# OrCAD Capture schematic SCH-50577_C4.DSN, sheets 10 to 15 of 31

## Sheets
10 08 SD Card: size C
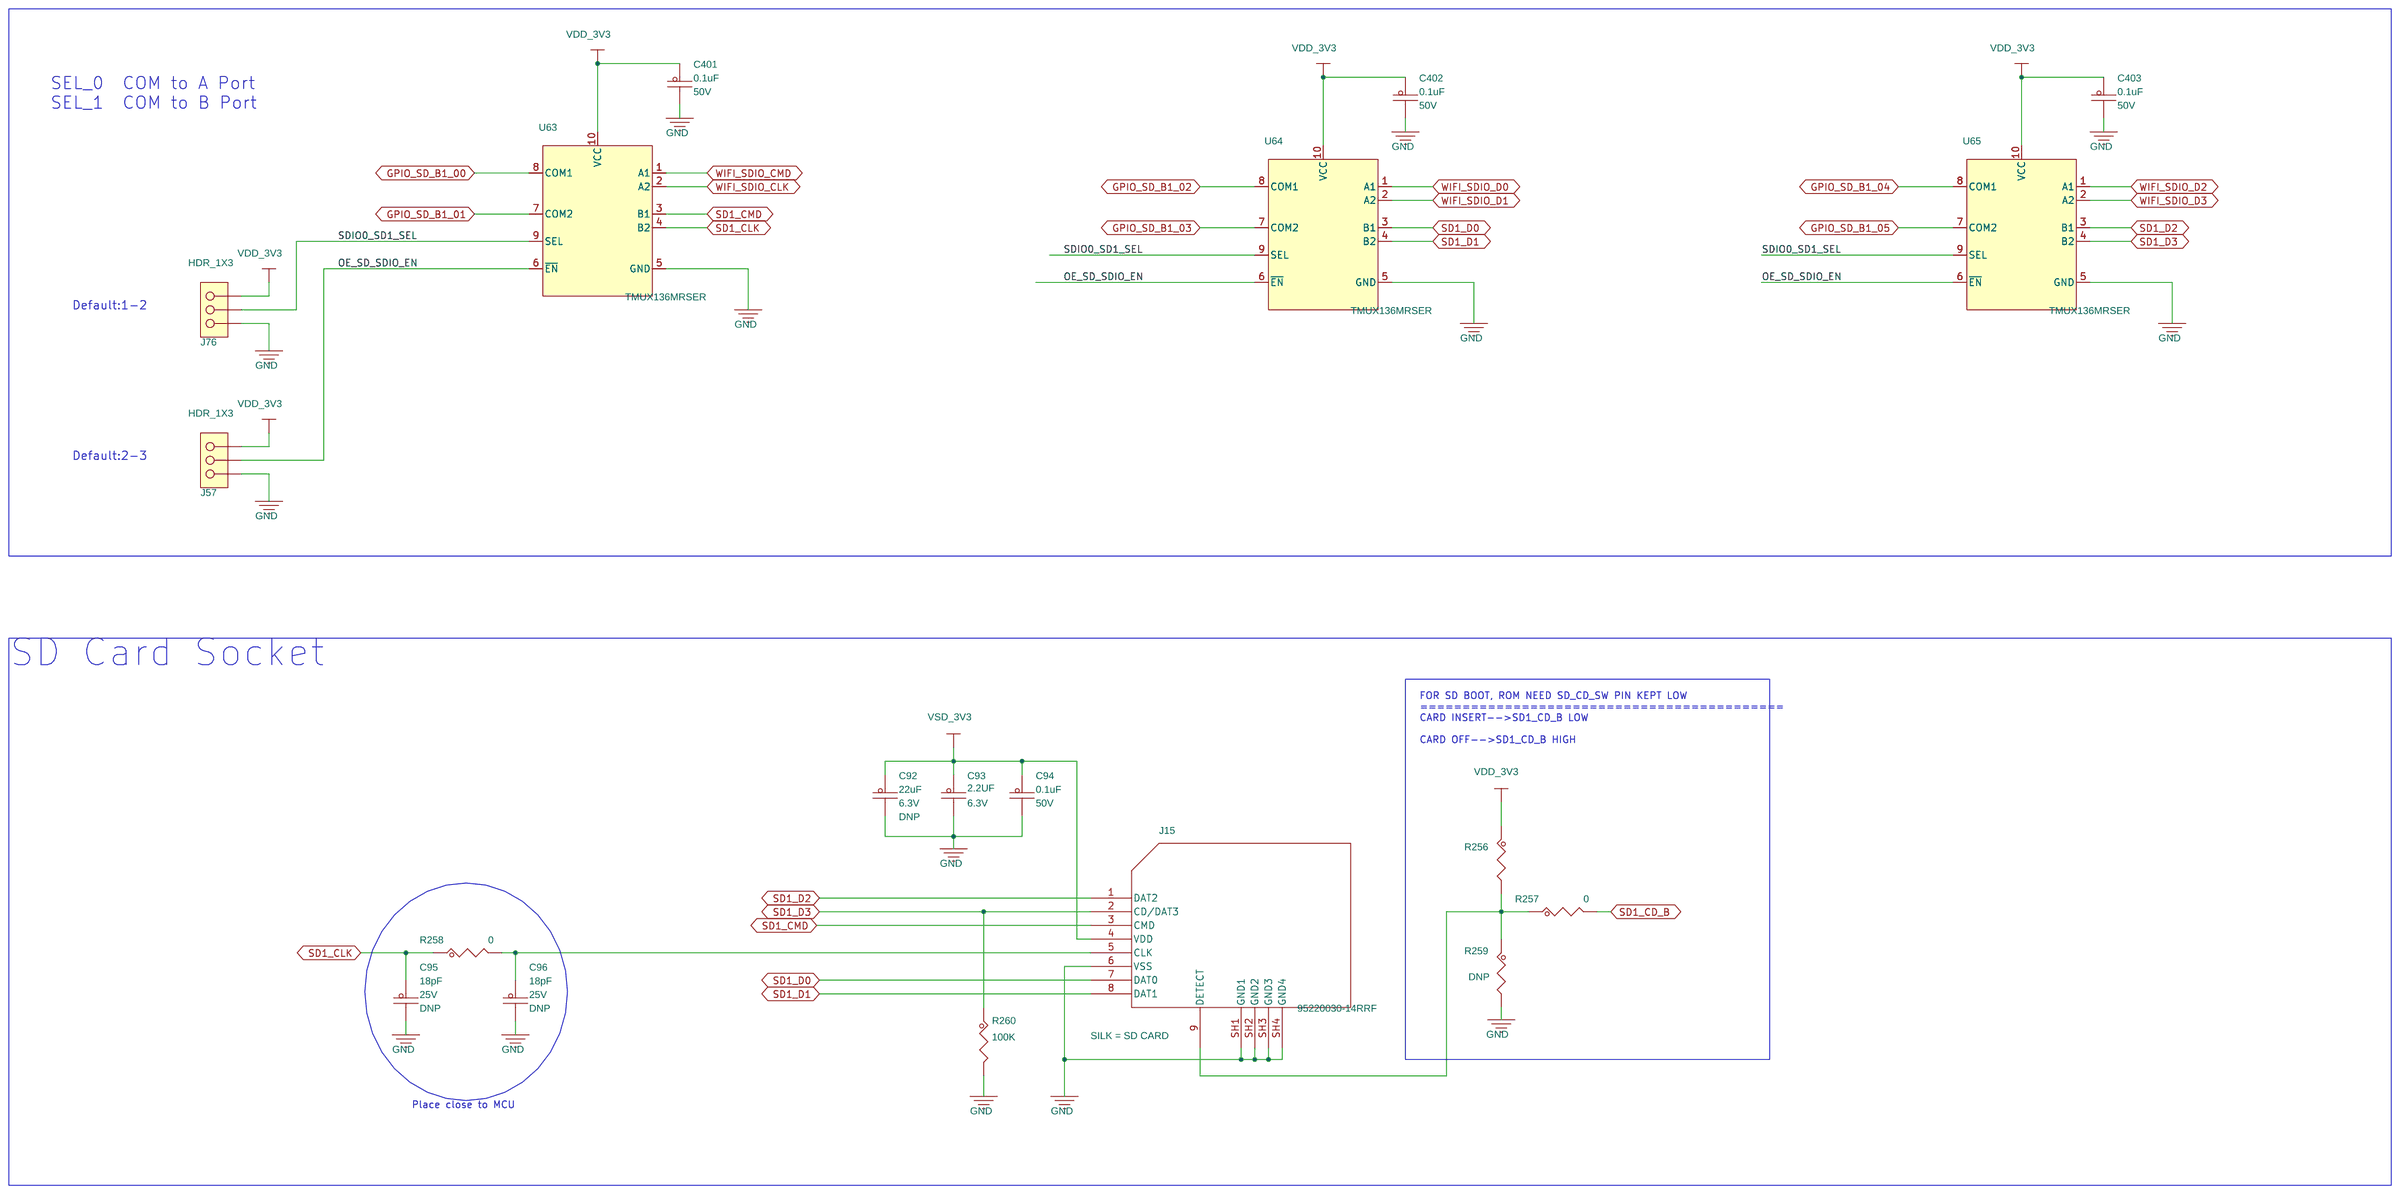
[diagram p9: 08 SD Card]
11 09 FLEXSPI Flash: size C
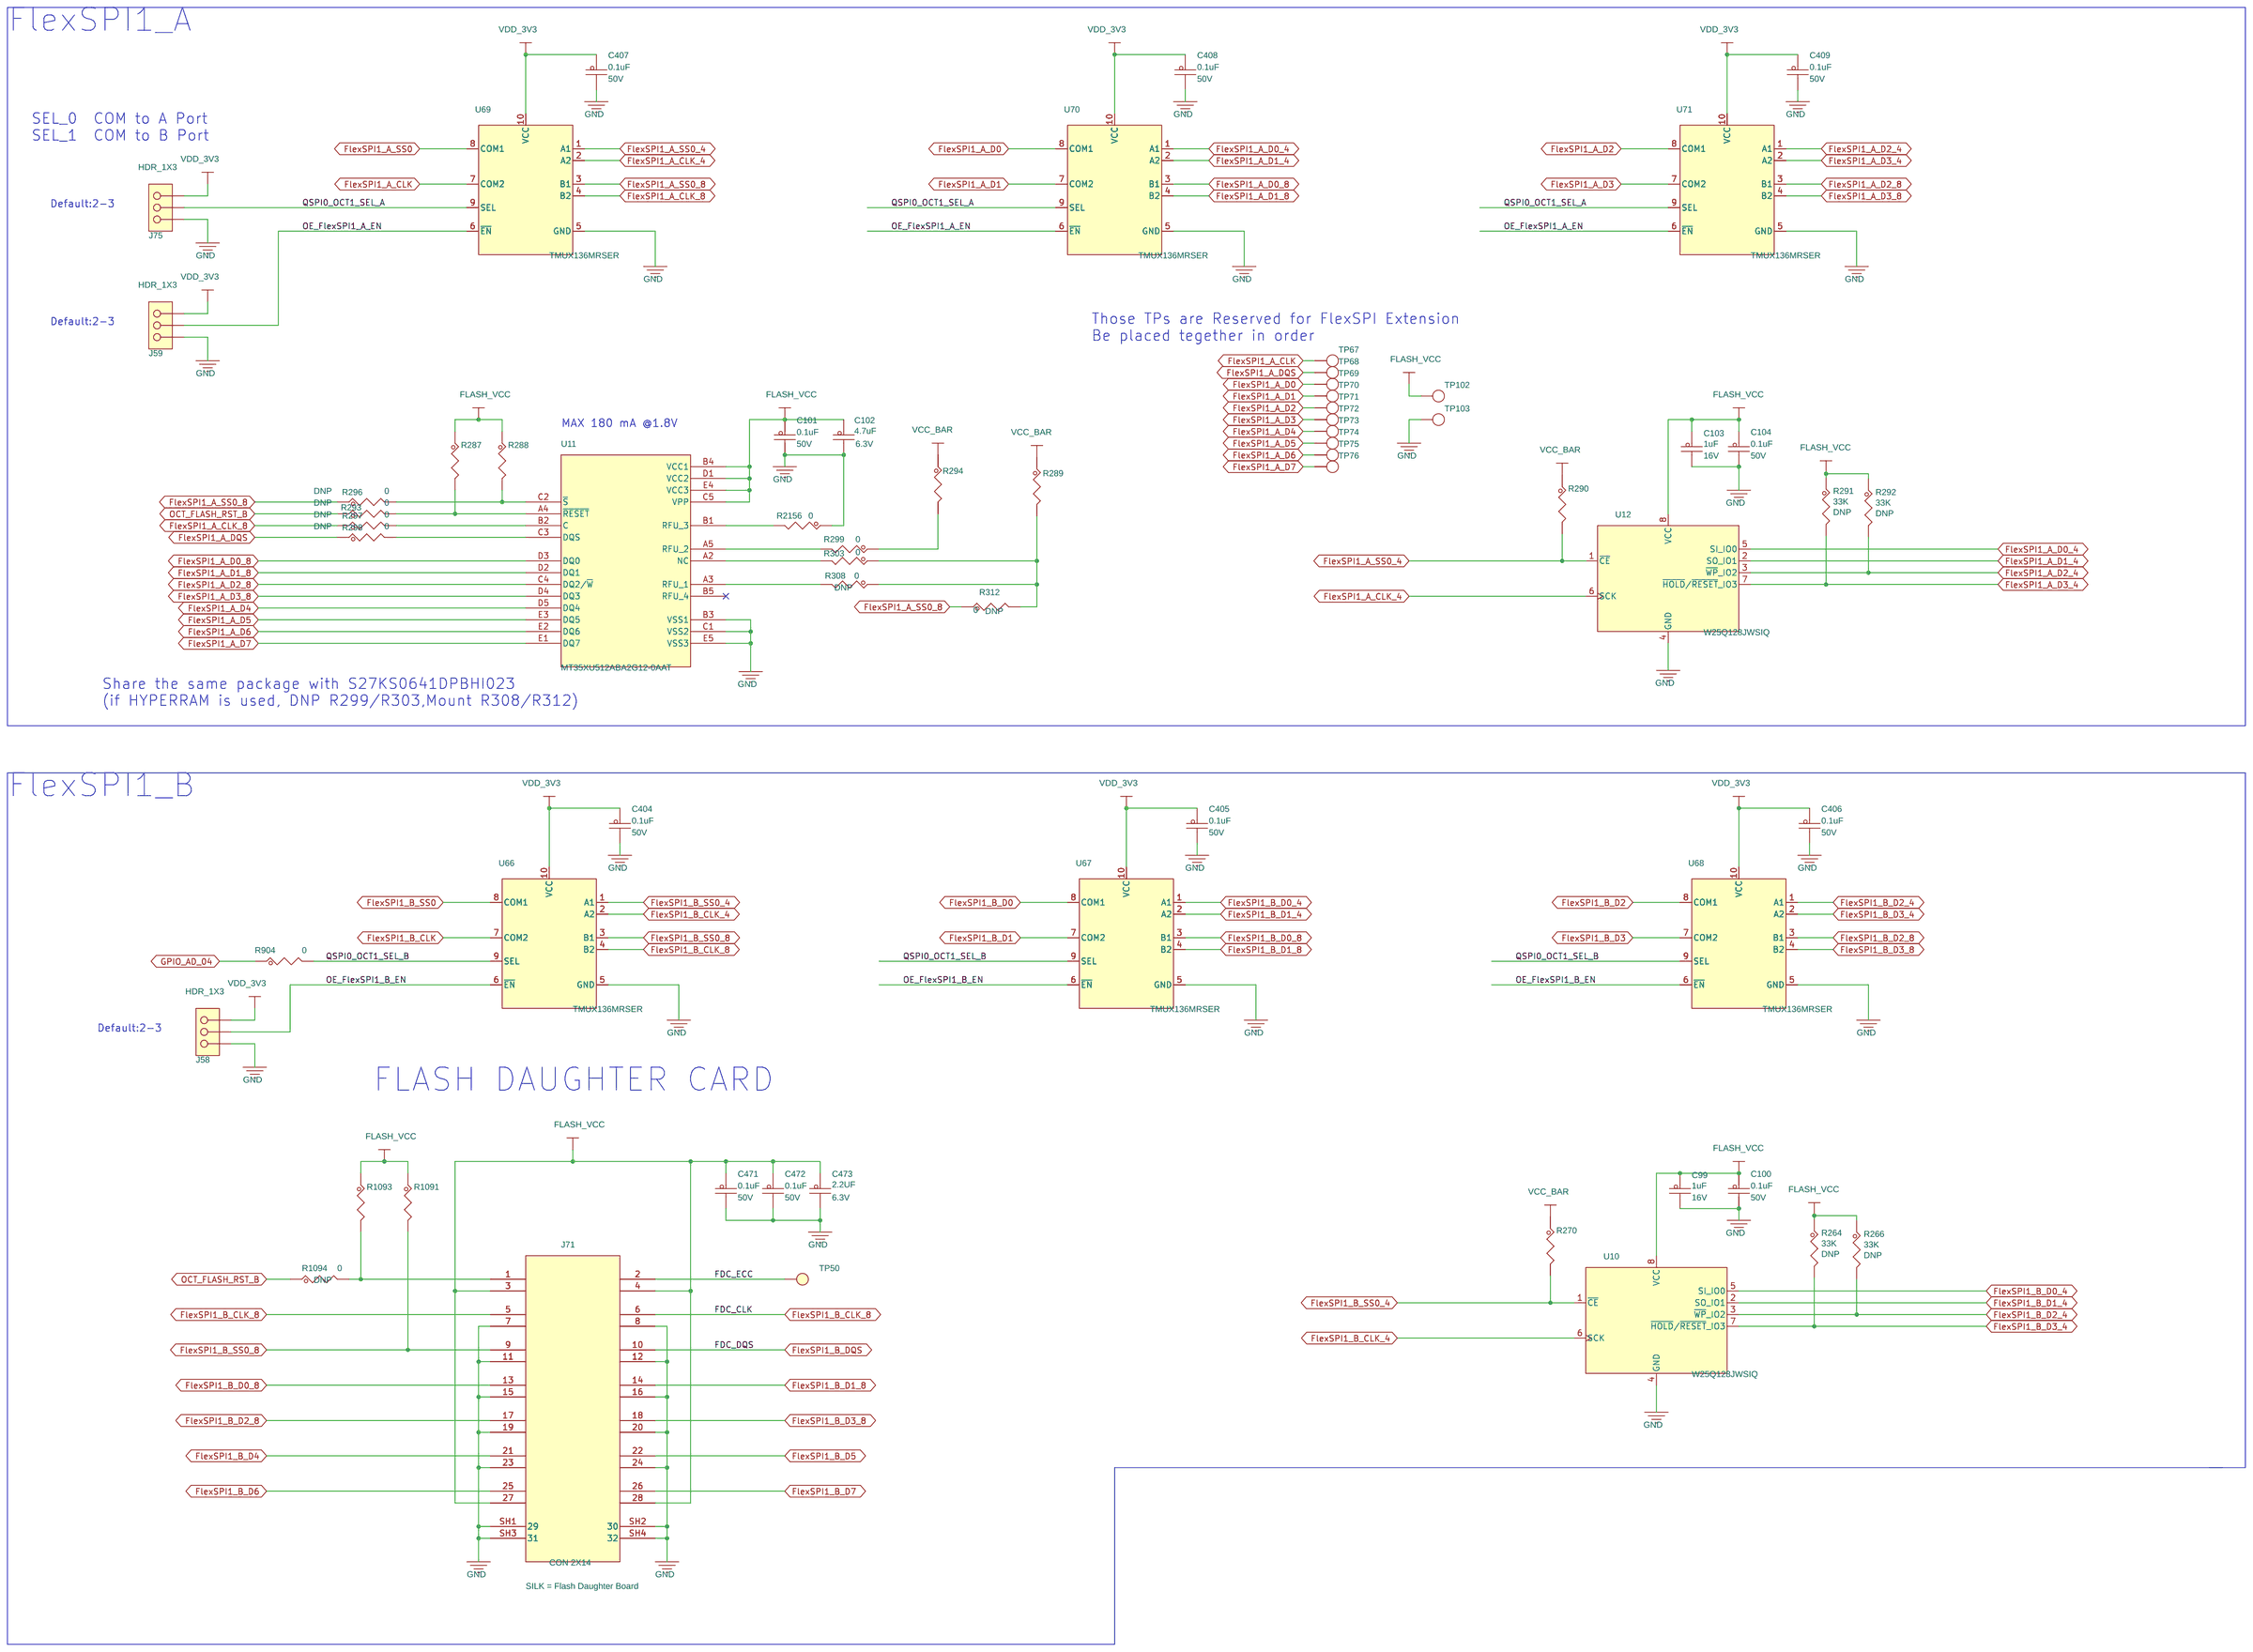
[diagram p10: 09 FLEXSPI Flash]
12 10 LPSPI Flash: size C
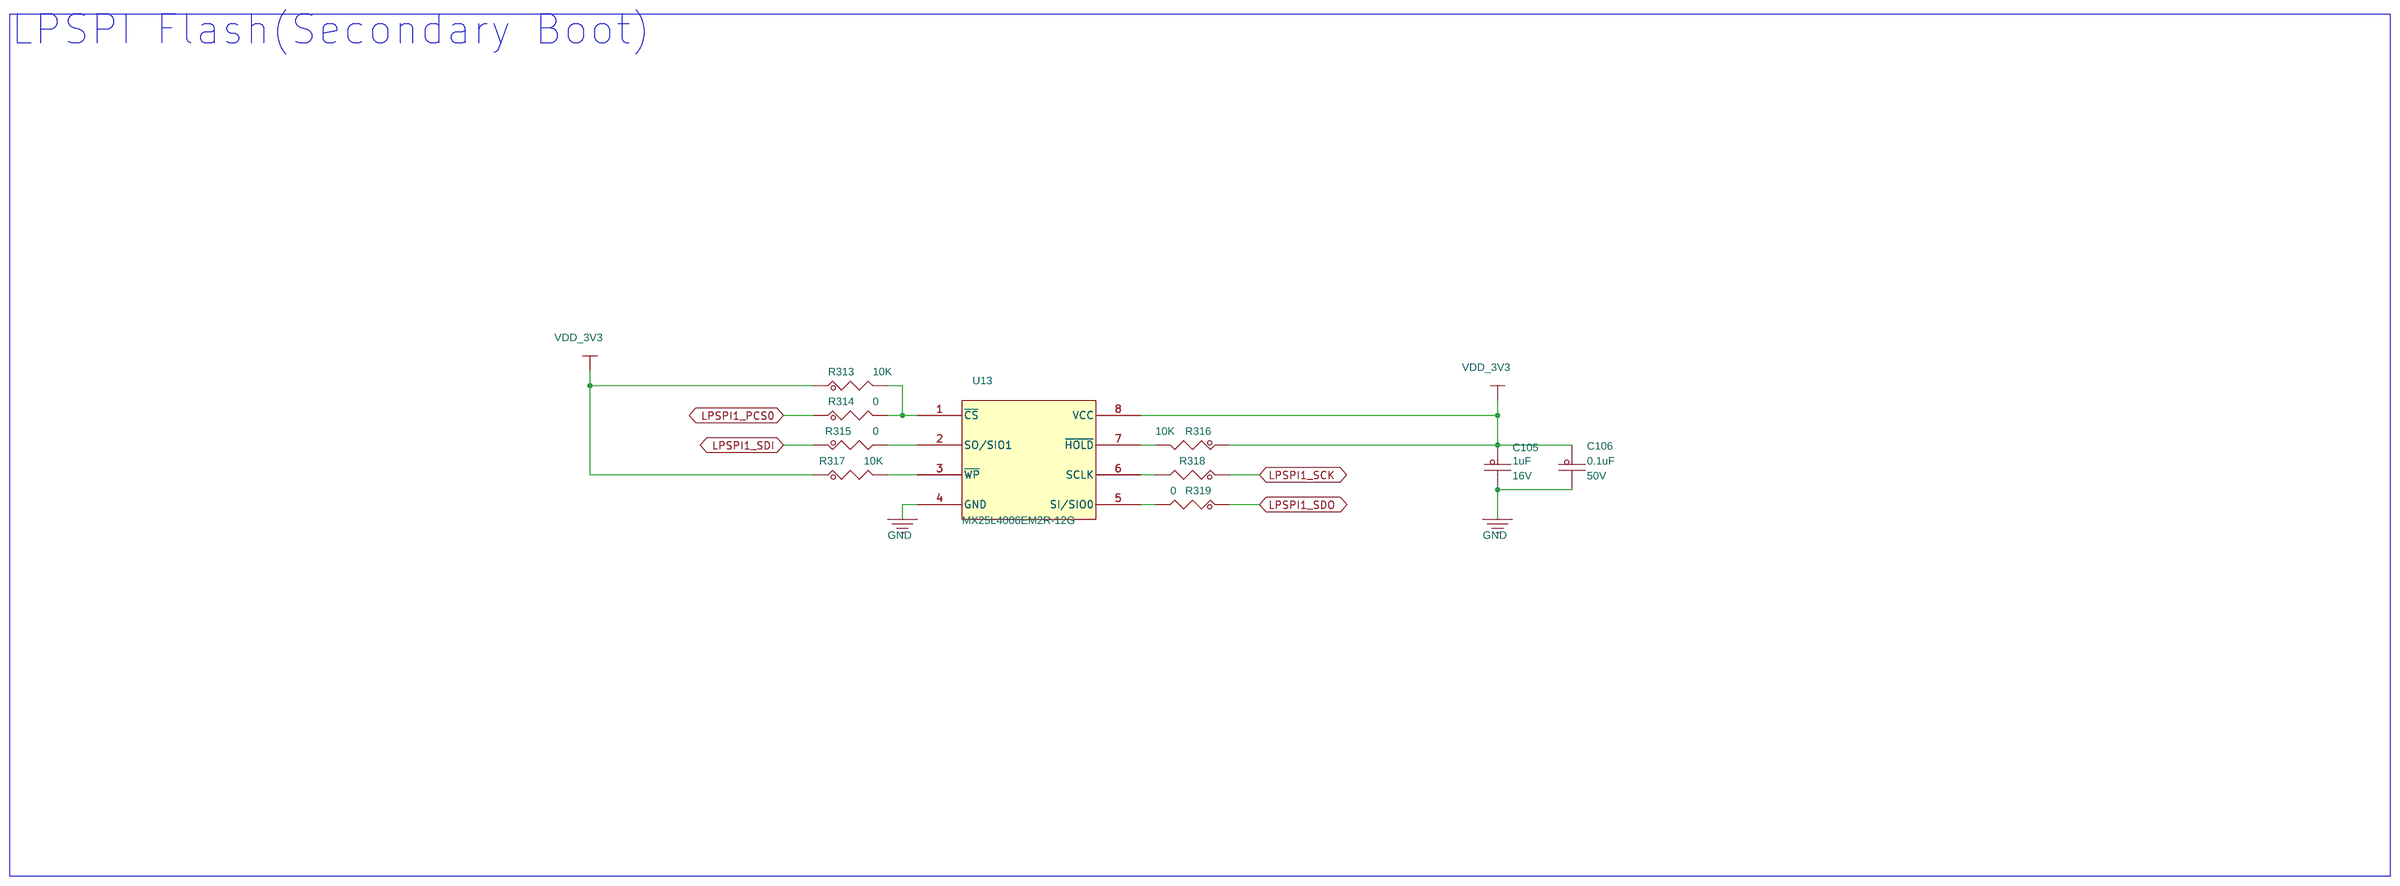
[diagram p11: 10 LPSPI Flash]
13 12 DMIC: size C
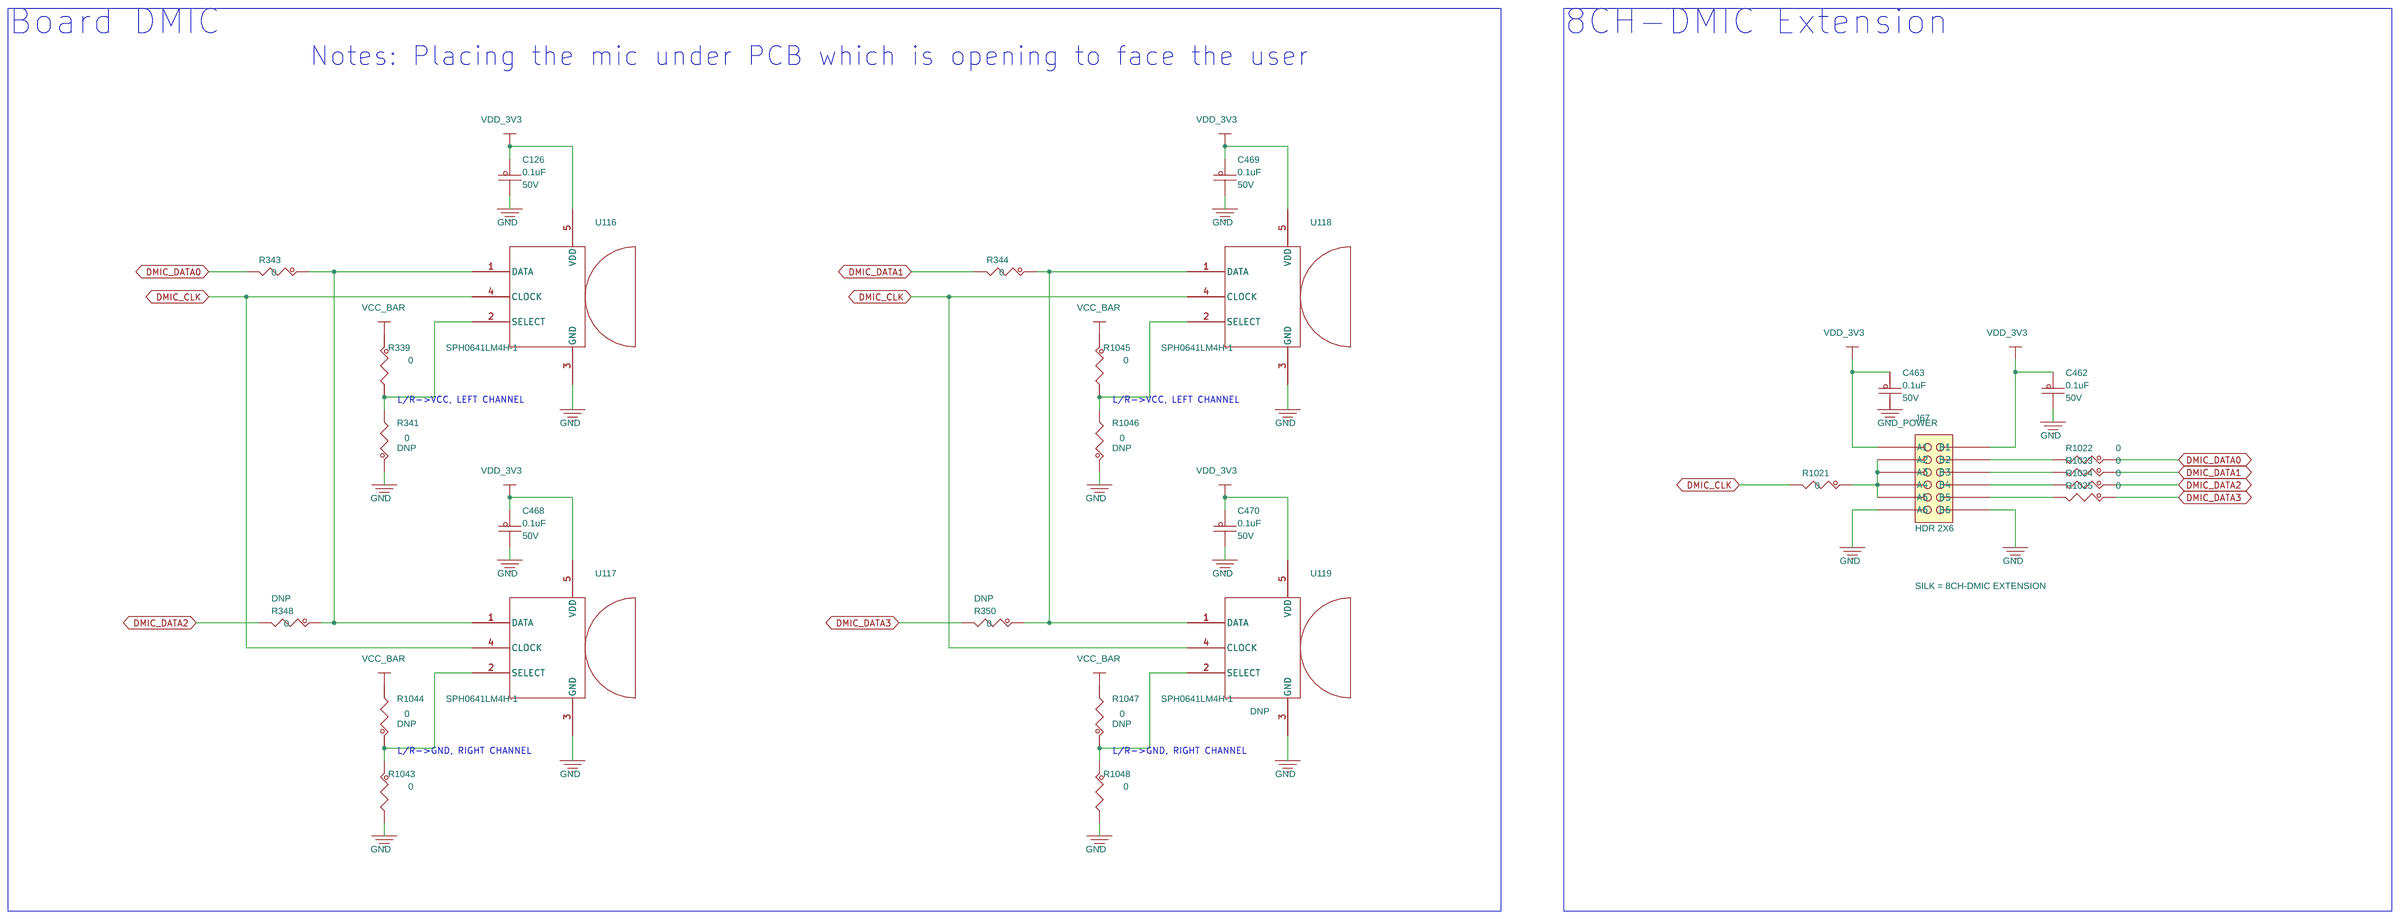
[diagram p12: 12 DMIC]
14 13 SAI: size C
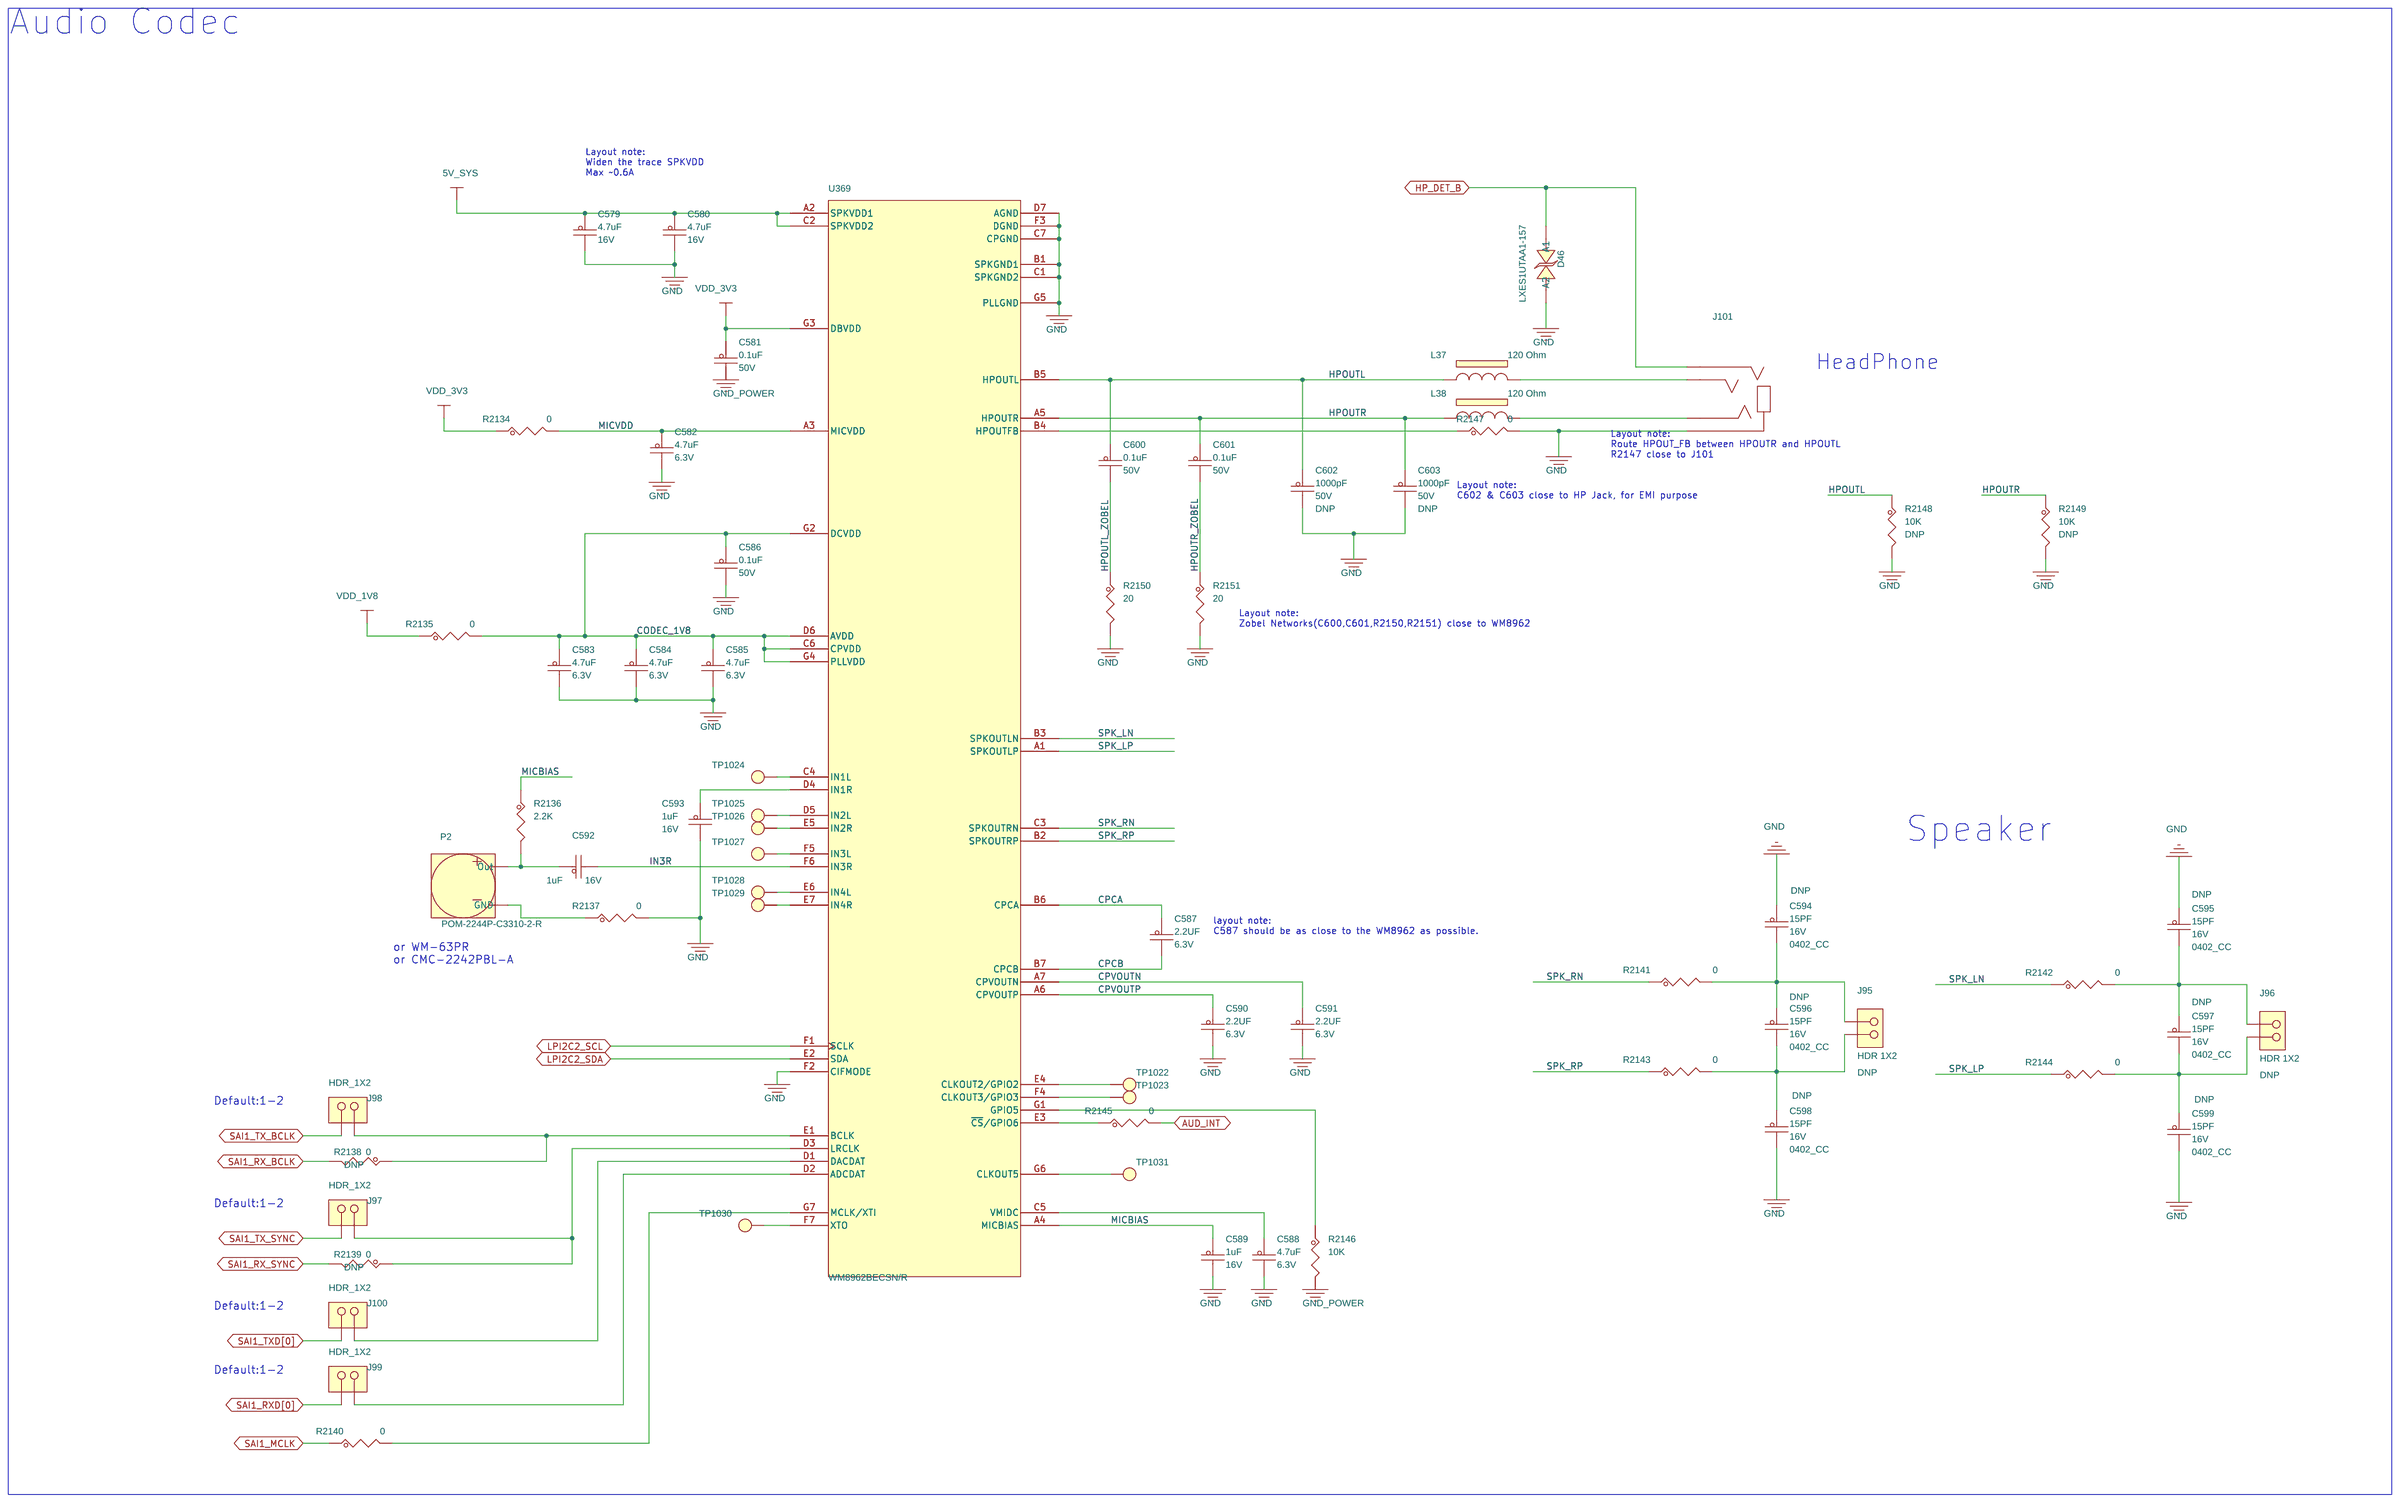
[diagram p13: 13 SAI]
15 14 SPDIF: size C
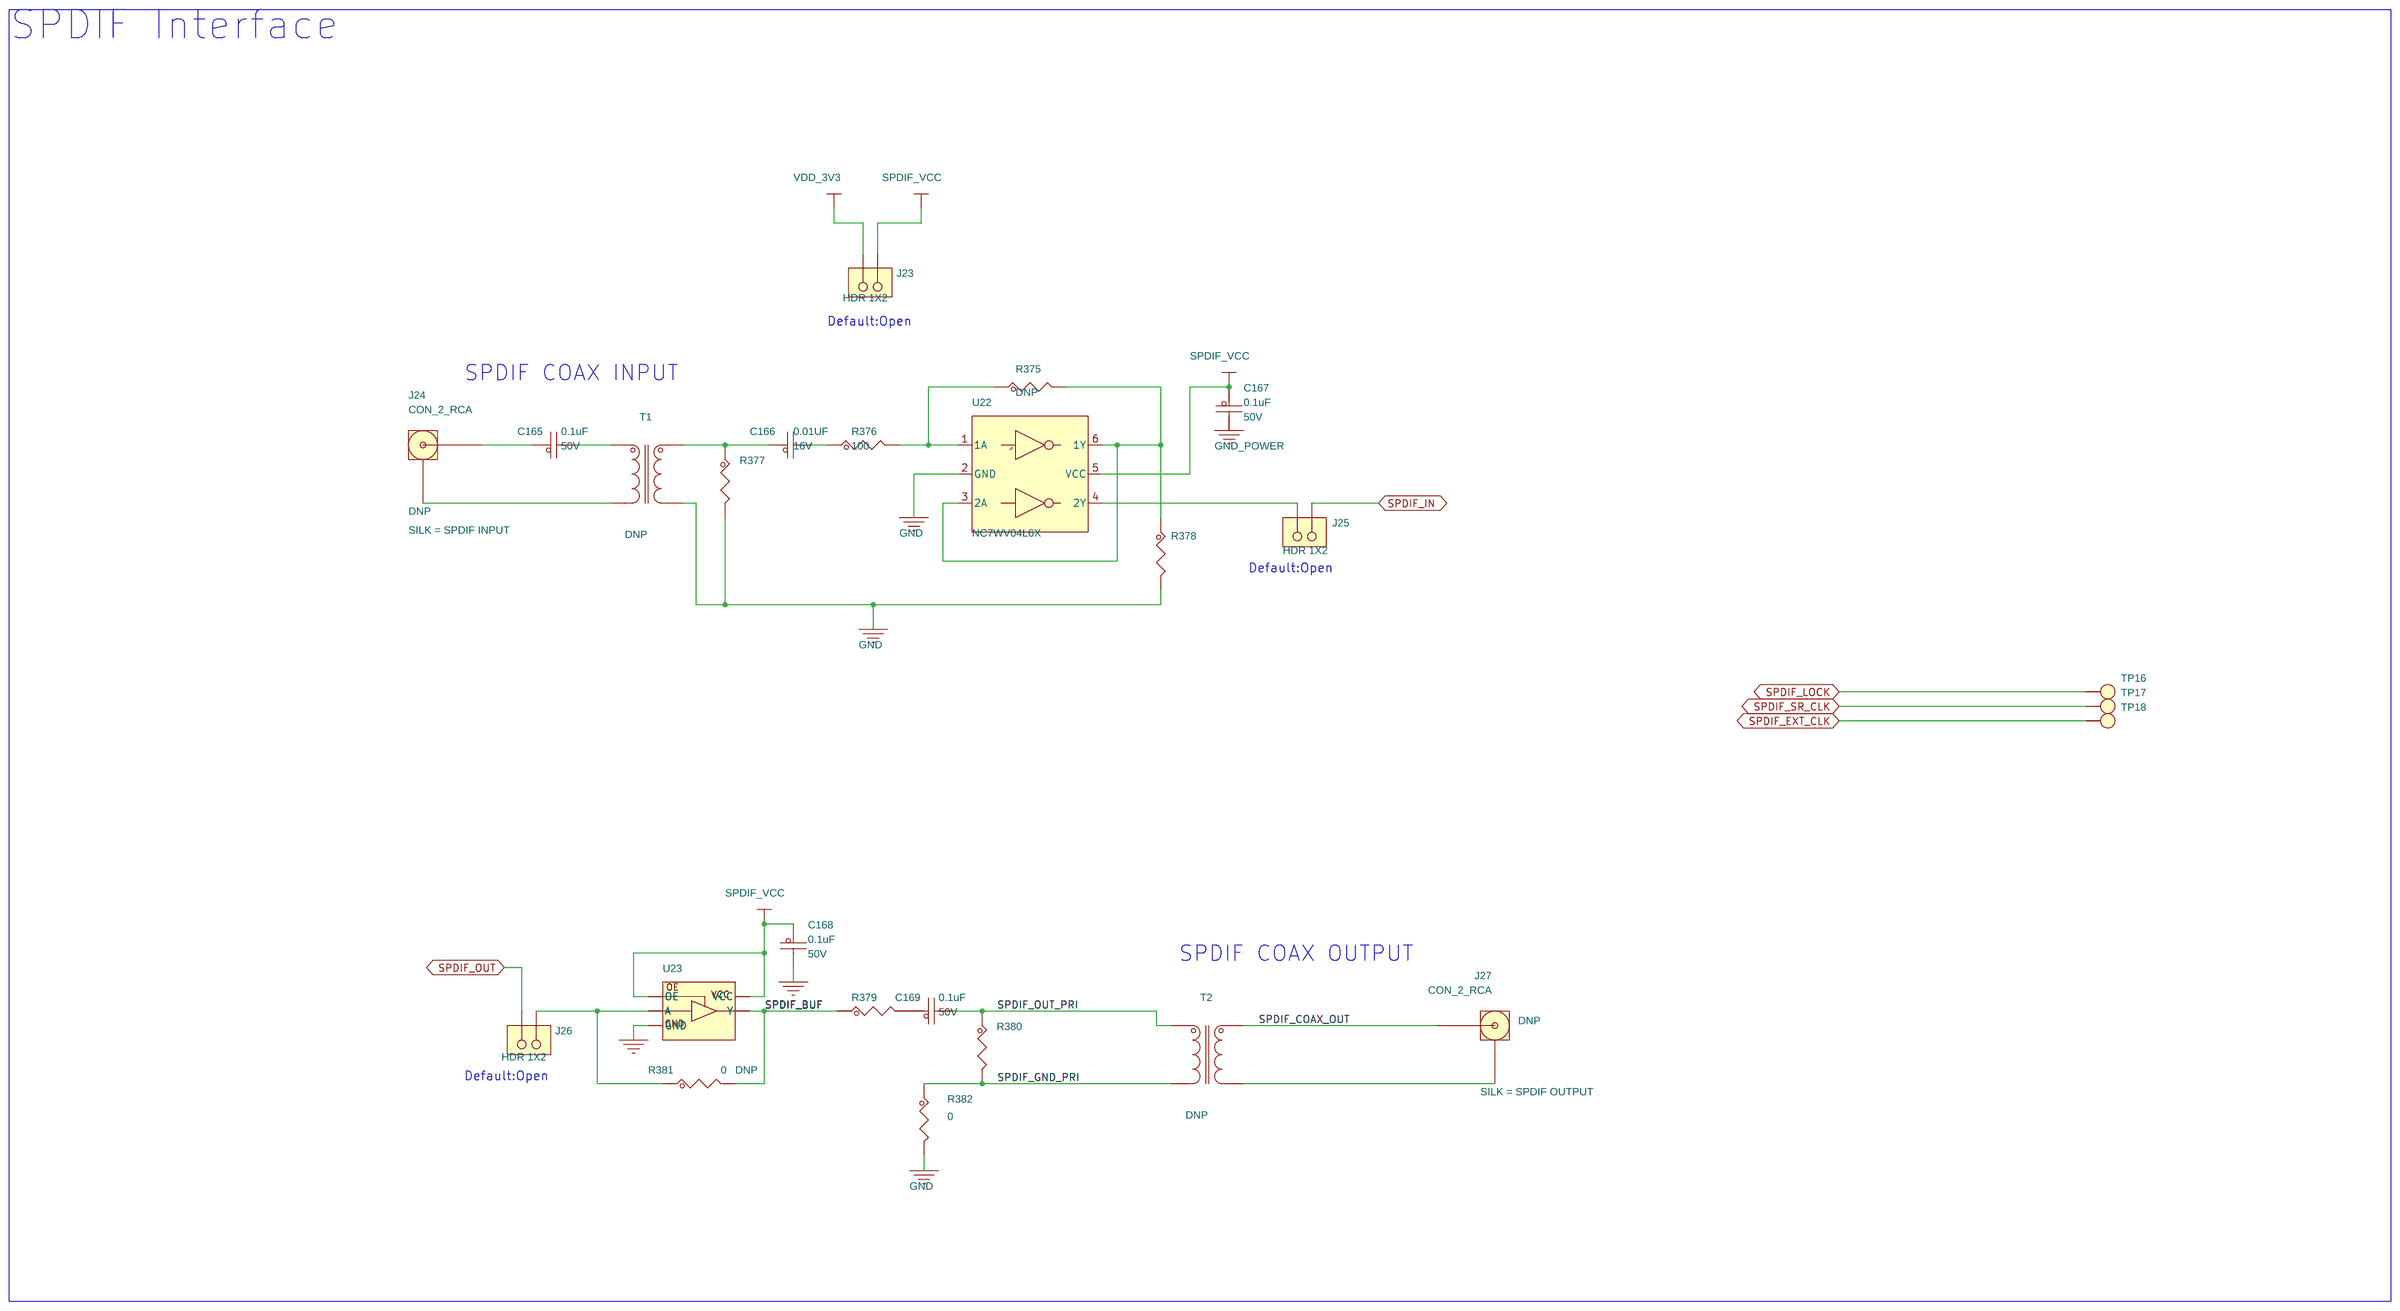
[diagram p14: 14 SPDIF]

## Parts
sheet 08 SD Card
C92  22uF  [CC0603_OV]
C93  2.2UF  [0402_CC]
C94  0.1uF  [0402_CC]
C95  18pF  [0402_CC]
C96  18pF  [0402_CC]
C401  0.1uF  [0402_CC]
C402  0.1uF  [0402_CC]
C403  0.1uF  [0402_CC]
J15  95220030-14RRF  [CON_SDCARD_95220]
J57  HDR_1X3  [HDR103]
J76  HDR_1X3  [HDR103]
R256  10K  [0402_CC]
R257  0  [0402_CC]
R258  0  [0402_CC]
R259  10K  [0402_CC]
R260  100K  [0402_CC]
U63  TMUX136MRSER  [uqfn10_0p5_2p05x1p55]
U64  TMUX136MRSER  [uqfn10_0p5_2p05x1p55]
U65  TMUX136MRSER  [uqfn10_0p5_2p05x1p55]
sheet 09 FLEXSPI Flash
C99  1uF  [0402_CC]
C100  0.1uF  [0402_CC]
C101  0.1uF  [0402_CC]
C102  4.7uF  [cc0402_tol0p15]
C103  1uF  [0402_CC]
C104  0.1uF  [0402_CC]
C404  0.1uF  [0402_CC]
C405  0.1uF  [0402_CC]
C406  0.1uF  [0402_CC]
C407  0.1uF  [0402_CC]
C408  0.1uF  [0402_CC]
C409  0.1uF  [0402_CC]
C471  0.1uF  [0402_CC]
C472  0.1uF  [0402_CC]
C473  2.2UF  [0402_CC]
J58  HDR_1X3  [HDR103]
J59  HDR_1X3  [HDR103]
J71  CON 2X14  [con_014_qse_dp_f]
J75  HDR_1X3  [HDR103]
R264  33K  [0402_CC]
R266  33K  [0402_CC]
R270  10K  [0402_CC]
R287  10K  [0402_CC]
R288  10K  [0402_CC]
R289  10K  [0402_CC]
R290  10K  [0402_CC]
R291  33K  [0402_CC]
R292  33K  [0402_CC]
R293  0  [0402_CC]
R294  10K  [0402_CC]
R296  0  [0402_CC]
R297  0  [0402_CC]
R298  0  [0402_CC]
R299  0  [0402_CC]
R303  0  [0402_CC]
R308  0  [0402_CC]
R312  0  [0402_CC]
R904  0  [0402_CC]
R1091  10K  [0402_CC]
R1093  10K  [0402_CC]
R1094  0  [0402_CC]
R2156  0  [0402_CC]
TP50  TPAD_050  [TPAD_050]
TP67  TPAD_030  [TPAD_030]
TP68  TPAD_030  [TPAD_030]
TP69  TPAD_030  [TPAD_030]
TP70  TPAD_030  [TPAD_030]
TP71  TPAD_030  [TPAD_030]
TP72  TPAD_030  [TPAD_030]
TP73  TPAD_030  [TPAD_030]
TP74  TPAD_030  [TPAD_030]
TP75  TPAD_030  [TPAD_030]
TP76  TPAD_030  [TPAD_030]
TP102  TPAD_030  [TPAD_030]
TP103  TPAD_030  [TPAD_030]
U10  W25Q128JWSIQ  [so8-25x75-200]
U11  MT35XU512ABA2G12-0AAT  [pbga24_1_6x8mm]
U12  W25Q128JWSIQ  [so8-25x75-200]
U66  TMUX136MRSER  [uqfn10_0p5_2p05x1p55]
U67  TMUX136MRSER  [uqfn10_0p5_2p05x1p55]
U68  TMUX136MRSER  [uqfn10_0p5_2p05x1p55]
U69  TMUX136MRSER  [uqfn10_0p5_2p05x1p55]
U70  TMUX136MRSER  [uqfn10_0p5_2p05x1p55]
U71  TMUX136MRSER  [uqfn10_0p5_2p05x1p55]
sheet 10 LPSPI Flash
C105  1uF  [0402_CC]
C106  0.1uF  [0402_CC]
R313  10K  [0402_CC]
R314  0  [0402_CC]
R315  0  [0402_CC]
R316  10K  [0402_CC]
R317  10K  [0402_CC]
R318  0  [0402_CC]
R319  0  [0402_CC]
U13  MX25L4006EM2R-12G  [SO8-25X75-200]
sheet 12 DMIC
C126  0.1uF  [0402_CC]
C462  0.1uF  [0402_CC]
C463  0.1uF  [0402_CC]
C468  0.1uF  [0402_CC]
C469  0.1uF  [0402_CC]
C470  0.1uF  [0402_CC]
J67  HDR 2X6  [hdr2x6_2p54_th]
R339  0  [0402_CC]
R341  0  [0402_CC]
R343  0  [0402_CC]
R344  0  [0402_CC]
R348  0  [0402_CC]
R350  0  [0402_CC]
R1021  0  [0402_CC]
R1022  0  [0402_CC]
R1023  0  [0402_CC]
R1024  0  [0402_CC]
R1025  0  [0402_CC]
R1043  0  [0402_CC]
R1044  0  [0402_CC]
R1045  0  [0402_CC]
R1046  0  [0402_CC]
R1047  0  [0402_CC]
R1048  0  [0402_CC]
U116  SPH0641LM4H-1  [mic5_3p6x2p75mm]
U117  SPH0641LM4H-1  [mic5_3p6x2p75mm]
U118  SPH0641LM4H-1  [mic5_3p6x2p75mm]
U119  SPH0641LM4H-1  [mic5_3p6x2p75mm]
sheet 13 SAI
C579  4.7uF  [CC0603_OV]
C580  4.7uF  [CC0603_OV]
C581  0.1uF  [CC0402_25]
C582  4.7uF  [cc0402_tol0p15]
C583  4.7uF  [cc0402_tol0p15]
C584  4.7uF  [cc0402_tol0p15]
C585  4.7uF  [cc0402_tol0p15]
C586  0.1uF  [CC0402_25]
C587  2.2UF  [CC0402_25]
C588  4.7uF  [cc0402_tol0p15]
C589  1uF  [CC0402_25]
C590  2.2UF  [CC0402_25]
C591  2.2UF  [CC0402_25]
C592  1uF  [CC0402_25]
C593  1uF  [CC0402_25]
C594  15PF  [0402_CC]
C595  15PF  [0402_CC]
C596  15PF  [0402_CC]
C597  15PF  [0402_CC]
C598  15PF  [0402_CC]
C599  15PF  [0402_CC]
C600  0.1uF  [CC0402_25]
C601  0.1uF  [CC0402_25]
C602  1000pF  [CC0402_25]
C603  1000pF  [CC0402_25]
D46  LXES1UTAA1-157  [dfn2_0p65_1p05x0p65mm]
J95  HDR 1X2  [HDR102]
J96  HDR 1X2  [HDR102]
J97  HDR_1X2  [hdr1x2_50mil]
J98  HDR_1X2  [hdr1x2_50mil]
J99  HDR_1X2  [hdr1x2_50mil]
J100  HDR_1X2  [hdr1x2_50mil]
J101  Audio Jack  [CON5_AUD_JACK_RA_TH_SJ-43514]
L37  120 Ohm  [IND_0402]
L38  120 Ohm  [IND_0402]
P2  POM-2244P-C3310-2-R  [mic_WM-63PR]
R2134  0  [0402_CC]
R2135  0  [0402_CC]
R2136  2.2K  [RC0402_25]
R2137  0  [0402_CC]
R2138  0  [0402_CC]
R2139  0  [0402_CC]
R2140  0  [0402_CC]
R2141  0  [0402_CC]
R2142  0  [0402_CC]
R2143  0  [0402_CC]
R2144  0  [0402_CC]
R2145  0  [0402_CC]
R2146  10K  [RC0402_25]
R2147  0  [0402_CC]
R2148  10K  [RC0402_25]
R2149  10K  [RC0402_25]
R2150  20  [RC0402_25]
R2151  20  [RC0402_25]
TP1022  TP_35MIL  [testpoint_35mil]
TP1023  TP_35MIL  [testpoint_35mil]
TP1024  TP_35MIL  [testpoint_35mil]
TP1025  TP_35MIL  [testpoint_35mil]
TP1026  TP_35MIL  [testpoint_35mil]
TP1027  TP_35MIL  [testpoint_35mil]
TP1028  TP_35MIL  [testpoint_35mil]
TP1029  TP_35MIL  [testpoint_35mil]
TP1030  TP_35MIL  [testpoint_35mil]
TP1031  TP_35MIL  [testpoint_35mil]
U369  WM8962BECSN/R  [BGA49_0P5_3P62X4]
sheet 14 SPDIF
C165  0.1uF  [0402_CC]
C166  0.01UF  [0402_CC]
C167  0.1uF  [0402_CC]
C168  0.1uF  [0402_CC]
C169  0.1uF  [0402_CC]
J23  HDR 1X2  [HDR102]
J24  CON_2_RCA  [con2_rca_ra_th]
J25  HDR 1X2  [HDR102]
J26  HDR 1X2  [HDR102]
J27  CON_2_RCA  [con2_rca_ra_th]
R375  10K  [0402_CC]
R376  100  [0402_CC]
R377  75.0  [RC0805_OV]
R378  10K  [0402_CC]
R379  374  [RC0805_OV]
R380  93.1  [RC0603_OV]
R381  0  [0402_CC]
R382  0  [0402_CC]
T1  TTWB1010L  [xfmr6_6p6x6p2]
T2  TTWB1010L  [xfmr6_6p6x6p2]
TP16  TP_35MIL  [testpoint_35mil]
TP17  TP_35MIL  [testpoint_35mil]
TP18  TP_35MIL  [testpoint_35mil]
U22  NC7WV04L6X  [MICROPAK_6P]
U23  NL17SZ126DF  [SC-70]

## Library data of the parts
C92 = CAP_NP: CAP CER 22uF 6.3V 20% X6S 0603; AGILE_PN: 150-79717; ASSY_OPT: DNP; CAD_APPROVED: Yes; FPLIST: CC0603_OV,CC0603,0603_CC_NSP; HEIGHT: 1MM; MFG_NAME01: MURATA; MFG_PN01: GRM188C80J226ME15D; Package Size: 0603; Package Type: 180mm ReelPAPER W8P4; ROHS: Yes; Tolerance: 20%; VOLTAGE: 6.3V
C93 C473 = CAP_NP: CAP CER 2.2UF 6.3V 10% X6S 0402; AGILE_PN: 150-80139; CAD_APPROVED: Yes; FPLIST: CC0402_25,CC0402_HD,0402_CC,capc0402_l; HEIGHT: 0.55MM; MFG_NAME01: MURATA; MFG_PN01: GRM155C80J225KE95D; ROHS: Yes; Temp Range: -55 to 105&#8451;; VOLTAGE: 6.3V
C94 C100 C101 C104 C106 C126 C165 C167-C169 C401-C409 C462 C463 C468-C472 = CAP_NP: CAP CER 0.1uF 50V 10% X7R AEC-Q200 0402; AGILE_PN: 150-79461; CAD_APPROVED: Yes; FPLIST: CC0402_25,CC0402_HD,0402_CC,CC0402_18,capc0402_l; HEIGHT: 0.55MM; MFG_NAME01: MURATA; MFG_PN01: GCM155R71H104KE02D; Package Size: 0402; ROHS: Yes; Tolerance: 10%; VOLTAGE: 50V
C95 C96 = CAP_NP: CAP CER 18pF 25V 5% C0G 0402; AGILE_PN: 150-78760; ASSY_OPT: DNP; CAD_APPROVED: Yes; FPLIST: CC0402_25,CC0402_HD,0402_CC; HEIGHT: 0.56MM; MFG_NAME01: AVX; MFG_PN01: 04023A180JAT2A; ROHS: Yes; TOL: 5%; Tolerance: 5%; VOLTAGE: 25V
J15 = CON8_SDCARD_DETECT: CON 8 SKT SD/MMC RA SMT 43MIL SP 84H AU; AGILE_PN: 211-80169; CAD_APPROVED: Yes; HEIGHT: 2.13MM; MFG_NAME01: ANYTRONIC CORPORATION LIMITED; ROHS: Yes; SILK: SD CARD; Temp Range: -25C to +85C; Temp_Range: -25C to +85C
J57-J59 J75 = CONN_HDR_3X1: HDR 1X3 TH 100MIL SP 338H AU 98L; AGILE_PN: 210-81491; CAD_APPROVED: Yes; HEIGHT: 8.59MM; Jumper(Default): 2-3; MFG_NAME01: ANYTRONIC CORPORATION LIMITED; MFG_PN01: 0901S0203011N9T-31RF; ROHS: Yes; Temp Range: -55°C to +105°C; Temp_Range: -55°C to +105°C
J76 = CONN_HDR_3X1: HDR 1X3 TH 100MIL SP 338H AU 98L; AGILE_PN: 210-81491; CAD_APPROVED: Yes; HEIGHT: 8.59MM; Jumper(Default): 1-2; MFG_NAME01: ANYTRONIC CORPORATION LIMITED; MFG_PN01: 0901S0203011N9T-31RF; ROHS: Yes; Temp Range: -55°C to +105°C; Temp_Range: -55°C to +105°C
R256 R270 R287-R290 R294 R378 R1091 R1093 = RES: RES MF 10K 1/16W 5% 0402; AGILE_PN: 470-75557; CAD_APPROVED: Yes; FPLIST: RC0402_25,RC0402_HD,0402_CC; HEIGHT: 0.4 MM; MFG_NAME01: VISHAY INTERTECHNOLOGY; MFG_PN01: CRCW040210K0JNED; ROHS: Yes; TOL: 5%; Tolerance: 5%
R257 R258 R299 R303 R339 R343 R344 R1021-R1025 R1043 R1045 R1048 R2134 R2135 R2137 R2140-R2145 R2147 R2156 = RES: RES MF ZERO OHM 1/16W 5% 0402; AGILE_PN: 470-75394; CAD_APPROVED: Yes; FPLIST: RC0402_25,RC0402_HD,RC0402_X2,0402_CC; HEIGHT: 0.45 MM; MFG_NAME01: ROHM; MFG_PN01: MCR01MZPJ000; ROHS: Yes; Tolerance: 5%; VOLTAGE: 1/16W
R259 R375 = RES: RES MF 10K 1/16W 5% 0402; AGILE_PN: 470-75557; ASSY_OPT: DNP; CAD_APPROVED: Yes; FPLIST: RC0402_25,RC0402_HD,0402_CC; HEIGHT: 0.4 MM; MFG_NAME01: VISHAY INTERTECHNOLOGY; MFG_PN01: CRCW040210K0JNED; ROHS: Yes; TOL: 5%; Tolerance: 5%
R260 = RES: RES MF 100K 1/16W 1% 0402; AGILE_PN: 470-76240; CAD_APPROVED: Yes; FPLIST: RC0402_25,RC0402_HD,0402_CC; HEIGHT: 0.4MM; MFG_NAME01: NIC COMPONENTS CORP; MFG_PN01: NRCL04F1003TRF; ROHS: Yes; Tolerance: 1%
U63-U71 = TMUX136_UQFN10: IC DUAL SPDT POWER 6GHz 2.3-4.8V UQFN10; AGILE_PN: 315-81880; CAD_APPROVED: Yes; HEIGHT: 0.6MM; MFG_NAME01: TEXAS INSTRUMENTS; ROHS: Yes; Temp Range: -40C to +85C; VOLTAGE: 2.3-4.8V
C99 C103 C105 = CAP_NP: CAP CER 1.0uF 16V 10% X6S 0402; AGILE_PN: 150-80262; CAD_APPROVED: Yes; FPLIST: CC0402_25,CC0402_HD,0402_CC,capc0402_l; HEIGHT: 0.55MM; MFG_NAME01: MURATA; MFG_PN01: GRM155C81C105KE11D; ROHS: Yes; Temp Range: -55°C to +105°C; Tolerance: 10%; VOLTAGE: 16V
C102 = CAP_NP: CAP CER 4.7uF 6.3V 20% X6S 0402; AGILE_PN: 150-81296; CAD_APPROVED: Yes; FPLIST: cc0402_tol0p15,cc0402_tol0p15_ov,cc0402_25_tol0p2,0402_cc_nsp; HEIGHT: 0.65MM; MFG_NAME01: MURATA; MFG_PN01: GRM155C80J475MEAA; Package Size: 0402 (1005 Metric); Package Type: SMD/SMT; ROHS: Yes; Rated Voltage: 6.3V; Temp Range: -55°C to +105°C; Tolerance: 20%; VOLTAGE: 6.3V
J71 = QSE_014_DP: CON 2X14 SKT SMT 0.8MM SP 130H AU; AGILE_PN: 211-81282; CAD_APPROVED: Yes; HEIGHT: 3.302 MM; MFG_NAME01: Samtec Inc.; MFG_PN01: QSE-014-01-F-D-DP-A; Package Type: Surface Mount; ROHS: Yes; SILK: Flash Daughter Board; Temp Range: -55C - 125C
R264 R266 R291 R292 = RES: RES MF 33K  1/16W 1% 0402; AGILE_PN: 470-31004; ASSY_OPT: DNP; CAD_APPROVED: Yes; FPLIST: RC0402_25,RC0402_HD,0402_CC; HEIGHT: 0.40 MM; MFG_NAME01: YAGEO AMERICA; MFG_PN01: RC0402FR-0733KL; ROHS: Yes; Temp Range: -55°C ~ 155°C; Temp_Range: -55°C ~ 155°C; Tolerance: 1%
R293 R296-R298 R308 R312 R341 R348 R350 R1044 R1046 R1047 R1094 R2138 R2139 = RES: RES MF ZERO OHM 1/16W 5% 0402; AGILE_PN: 470-75394; ASSY_OPT: DNP; CAD_APPROVED: Yes; FPLIST: RC0402_25,RC0402_HD,RC0402_X2,0402_CC; HEIGHT: 0.45 MM; MFG_NAME01: ROHM; MFG_PN01: MCR01MZPJ000; ROHS: Yes; Tolerance: 5%; VOLTAGE: 1/16W
R314 R315 R318 R319 R382 R904 = RES: RES MF ZERO OHM 1/16W 5% 0402; AGILE_PN: 470-75394; CAD_APPROVED: Yes; FPLIST: RC0402_25,RC0402_HD,RC0402_X2,0402_CC; HEIGHT: 0.45 MM; MFG_NAME01: YAGEO AMERICA; MFG_PN01: RC0402JR-070RL; ROHS: Yes; Tolerance: 5%; VOLTAGE: 1/16W
TP50 = TEST_POINT_L: TEST POINT PAD 50MIL DIA SMT, NO PART TO ORDER; AGILE_PN: 211-76644; CAD_APPROVED: Yes; EN: 666-1-00186; HEIGHT: 0.1MM; KEY Number: 666-1-00186@1; MFG_NAME01: NOTACOMPONENT; MFG_PN01: NOTACOMPONENT; Mfg: NA; Mfg Part No: 666-1-00186; ROHS: Yes
TP67-TP76 TP102 TP103 = TestLoop: TEST POINT PAD 30MIL DIA SMT, NO PART TO ORDER; 3D_Mechanical_Footprint_File: ftp://fcl.am.freescale.net/ALLEGRO/step/tpad_030.STEP; AGILE_PN: 211-76642; CAD_APPROVED: Yes; HEIGHT: 0.1MM; MFG_NAME01: NOTACOMPONENT; MFG_PN01: NOTACOMPONENT; ROHS: Yes
U10 U12 = 25WP_8P: IC MEM SERIAL FLASH NOR DUAL/QUAD SPI 128MBIT 133MHz 1.7-1.95V SOIC8; 3D_Mechanical_Footprint_File: ftp://fcl.am.freescale.net/ALLEGRO/step/so8-25x75-200.STEP; AGILE_PN: 342-00906; CAD_APPROVED: Yes; FPLIST: so8-25x75-200,so8_w; HEIGHT: 2.16MM; MFG_NAME01: WINBOND ELECTRONICS CORP; Package Size: 8-SOIC (0.209", 5.30mm Width); ROHS: Yes; Supply Voltage: 1.7-1.95V; Temp Range: -40°C to +85°C; VOLTAGE: 1.7-1.95V
U11 = MT35X_TBGA24: IC MEM FLASH SERIAL 512Mb 1.7-2.0V AEC-Q100 T-PBGA24; 3D_Mechanical_Footprint_File: ftp://fcl.am.freescale.net/ALLEGRO/step/pbga24_1_6x8mm.STEP; AGILE_PN: 342-00923; CAD_APPROVED: Yes; HEIGHT: 1.2MM; MFG_NAME01: MICRON; Package Size: T-PBGA-24; ROHS: Yes; Supply Voltage: 1.7-2.0V; Temp Range: -40°C to +105°C; VOLTAGE: 1.7-2.0V
R313 R316 R317 R2146 = RES: RES MF 10K 1/16W 5% 0402; AGILE_PN: 470-75557; CAD_APPROVED: Yes; FPLIST: RC0402_25,RC0402_HD,0402_CC; HEIGHT: 0.4 MM; MFG_NAME01: VISHAY INTERTECHNOLOGY; MFG_PN01: CRCW040210K0JNED; ROHS: Yes; Tolerance: 5%
U13 = MX25L6406EM2I_SOP8: IC MEM FLASH SPI 4MBIT 86MHZ 2.7-3.6V AUTOMOTIVE SOP8; AGILE_PN: 334-77823; CAD_APPROVED: Yes; HEIGHT: 2.16MM; MFG_NAME01: MACRONIX INTERNATIONAL CO., LTD; ROHS: Yes; Temp Range: -40°C ~ 105°C; Temp_Range: -40°C ~ 105°C; VOLTAGE: 2.7-3.6V
J67 = CONN_HDR_6X2: HDR 2X6 TH 100MIL CTR 344H AU 118L; 3D_Mechanical_Footprint_File: ftp://fcl.am.freescale.net/ALLEGRO/step/hdr2x6_2p54_th.STEP; AGILE_PN: 210-81939; CAD_APPROVED: Yes; HEIGHT: 8.74MM; MFG_NAME01: WURTH ELEKTRONIK EISOS GMBH & CO. KG (ELECTRONIC & ELECTROMEHANICAL COMP); MFG_PN01: 61301221121; ROHS: Yes; SILK: 8CH-DMIC EXTENSION; Temp Range: -40°C to 105°C; Temp_Range: -40°C to 105°C
U116-U118 = MIC_SPH0641LM4H-1_5P: MICROPHONE DIGITAL ZERO HEIGHT SISONIC 64DB -0.3-5V SMT; AGILE_PN: 510-78168; CAD_APPROVED: Yes; HEIGHT: 1.08MM; MFG_NAME01: KNOWLES ACOUSTICS; ROHS: Yes; Temp Range: -40C to +100C
U119 = MIC_SPH0641LM4H-1_5P: MICROPHONE DIGITAL ZERO HEIGHT SISONIC 64DB -0.3-5V SMT; AGILE_PN: 510-78168; ASSY_OPT: DNP; CAD_APPROVED: Yes; HEIGHT: 1.08MM; MFG_NAME01: KNOWLES ACOUSTICS; ROHS: Yes; Temp Range: -40C to +100C
C579 C580 = CAP_NP: CAP CER 4.7uF 16V 10% X7R 0603; AGILE_PN: 150-80123; CAD_APPROVED: Yes; FPLIST: CC0603_OV,CC0603,0603_cc_tol,cc0603_0805_nsp; HEIGHT: 1MM; MFG_NAME01: MURATA; MFG_PN01: GRM188Z71C475KE21; Package Size: 0603; ROHS: Yes; Rated Voltage: 16V; Temp Range: -55C to +125C; Tolerance: 10%
C581 C586 C600 C601 = CAP_NP: CAP CER 0.1uF 50V 10% X7R AEC-Q200 0402; AGILE_PN: 150-79461; CAD_APPROVED: Yes; FPLIST: CC0402_25,CC0402_HD,0402_CC,CC0402_18,capc0402_l; HEIGHT: 0.55MM; MFG_NAME01: MURATA; MFG_PN01: GCM155R71H104KE02D; Package Size: 0402; ROHS: Yes; Rated Voltage: 50V; Temp Range: -55C to +125C; Tolerance: 10%
C582-C585 C588 = CAP_NP: CAP CER 4.7uF 6.3V 20% X6S 0402; AGILE_PN: 150-81296; CAD_APPROVED: Yes; FPLIST: cc0402_tol0p15,cc0402_tol0p15_ov,cc0402_25_tol0p2,0402_cc_nsp; HEIGHT: 0.65MM; MFG_NAME01: MURATA; MFG_PN01: GRM155C80J475MEAA; Package Size: 0402 (1005 Metric); Package Type: SMD/SMT; ROHS: Yes; Rated Voltage: 6.3V; Temp Range: -55C to +105C; Tolerance: 20%
C587 C590 C591 = CAP_NP: CAP CER 2.2UF 6.3V 10% X6S 0402; AGILE_PN: 150-80139; CAD_APPROVED: Yes; FPLIST: CC0402_25,CC0402_HD,0402_CC,capc0402_l; HEIGHT: 0.55MM; MFG_NAME01: MURATA; MFG_PN01: GRM155C80J225KE95D; ROHS: Yes; Rated Voltage: 6.3V; Temp Range: -55C to +105C; Tolerance: 10%
C589 C592 C593 = CAP_NP: CAP CER 1.0uF 16V 10% X6S 0402; AGILE_PN: 150-80262; CAD_APPROVED: Yes; FPLIST: CC0402_25,CC0402_HD,0402_CC,capc0402_l; HEIGHT: 0.55MM; MFG_NAME01: MURATA; MFG_PN01: GRM155C81C105KE11D; ROHS: Yes; Rated Voltage: 16V; Temp Range: -55C to +105C; Tolerance: 10%
C594-C599 = CAP_NP: CAP CER 15PF 16V 5% C0G 0402; AGILE_PN: 150-75720; ASSY_OPT: DNP; CAD_APPROVED: Yes; FPLIST: CC0402_25,CC0402_HD,0402_CC; HEIGHT: 0.55MM; MFG_NAME01: KEMET; MFG_PN01: C0402C150J4GAC; Package Size: 0402; ROHS: Yes; Tolerance: 5%; VOLTAGE: 16V
C602 C603 = CAP_NP: CAP CER 1000PF 50V 5% C0G 0402; AGILE_PN: 150-76334; ASSY_OPT: DNP; CAD_APPROVED: Yes; FPLIST: CC0402_25,CC0402_HD,0402_CC,capc0402_l; HEIGHT: 0.55MM; MFG_NAME01: MURATA; MFG_PN01: GRM1555C1H102JA01D; Package Size: 0402; Package Type: 180mm Paper Tape; ROHS: Yes; Tolerance: 5%; VOLTAGE: 50V
D46 = DIODE_TVS_BIDIR: DIODE TVS 1mA 6V DFN2; AGILE_PN: 480-80368; CAD_APPROVED: YES; HEIGHT: 0.4 MM; MFG_NAME01: MURATA; ROHS: YES; Temp Range: -40C to +85C
J95 J96 = CONN_HDR_2X1: HDR 1X2 TH 100MIL SP 339H AU 98L; AGILE_PN: 210-81490; ASSY_OPT: DNP; CAD_APPROVED: Yes; HEIGHT: 8.59MM; MFG_NAME01: ANYTRONIC CORPORATION LIMITED; MFG_PN01: 0901S0202011N9T-31RF; ROHS: Yes; Temp Range: -55°C to +105°C; Temp_Range: -55°C to +105°C
J97-J100 = CONN_HDR_2X1: HDR 1X2 TH 50MIL SP 165H AU 91L; AGILE_PN: 210-80212; CAD_APPROVED: Yes; HEIGHT: 4.2MM; Jumper(Default): 1-2; MFG_NAME01: SULLINS ELECTRONICS CORP; MFG_PN01: GRPB021VWVN-RC; ROHS: Yes
J101 = 3.5MM_AUDIO_JACK: CON 1 AUD JACK 3.5MM RA TH 205H SN 86L; AGILE_PN: 210-79826; CAD_APPROVED: Yes; HEIGHT: 5.2MM; MFG_NAME01: CUI INC; MFG_PN01: SJ-43514; ROHS: Yes
L37 L38 = INDUCTOR_FERRITE: IND FER BEAD 120 OHM@100MHZ 0.5A 25% 0402; AGILE_PN: 180-77771; CAD_APPROVED: Yes; FPLIST: IND_0402,0402_CC; HEIGHT: 0.55MM; MFG_NAME01: MURATA; MFG_PN01: BLM15AG121SN1D; Package Size: 0402; ROHS: Yes
P2 = MIC_POM: AUDIO DEVICE MIC ELECTRET 0.5MA 2V -44+/-3DB 2.2KOHM 6MM TH; AGILE_PN: 510-77976; CAD_APPROVED: Yes; HEIGHT: 2.7 MM; MFG_NAME01: PUI AUDIO INC; ROHS: Yes
R2136 = RES: RES MF 2.2K 1/16W 5% 0402; AGILE_PN: 470-76602; CAD_APPROVED: Yes; FPLIST: RC0402_25,RC0402_HD,0402_CC; HEIGHT: 0.4 MM; MFG_NAME01: YAGEO AMERICA; MFG_PN01: RC0402JR-072K2L; ROHS: Yes; Tolerance: 5%
R2148 R2149 = RES: RES MF 10K 1/16W 5% 0402; AGILE_PN: 470-75557; ASSY_OPT: DNP; CAD_APPROVED: Yes; FPLIST: RC0402_25,RC0402_HD,0402_CC; HEIGHT: 0.4 MM; MFG_NAME01: VISHAY INTERTECHNOLOGY; MFG_PN01: CRCW040210K0JNED; ROHS: Yes; Tolerance: 5%
R2150 R2151 = RES: RES MF 20 OHM 1/10W 1% 0402; AGILE_PN: 470-80286; CAD_APPROVED: Yes; FPLIST: RC0402_25,RC0402_HD,0402_CC; HEIGHT: 0.40 MM; MFG_NAME01: PANASONIC; MFG_PN01: ERJ2RKF20R0X; ROHS: Yes; Tolerance: 1%
TP16-TP18 TP1022-TP1031 = T_POINT_R: TEST POINT PAD .035 SMT, no part to order; AGILE_PN: 510-75618; CAD_APPROVED: Yes; HEIGHT: 0.1MM; ROHS: Yes
U369 = WM8962_BGA_49P_CUST: IC AUDIO CODEC 24BIT DAC 2 CH ADC 1.8V BGA49; AGILE_PN: 315-80353; CAD_APPROVED: Yes; HEIGHT: 0.75MM; MFG_NAME01: WOLFSON MICROELECTRONICS; ROHS: Yes
C166 = CAP_NP: CAP CER 0.01UF 16V 20% X7R 0402; AGILE_PN: 150-30082; CAD_APPROVED: Yes; FPLIST: CC0402_25,CC0402_HD,0402_CC; HEIGHT: 0.56MM; MFG_NAME01: AVX; MFG_PN01: 0402YC103MAT2A; Package Size: 0402; ROHS: Yes; TOL: 20%; Tolerance: 20%; VOLTAGE: 16V
J23 J25 J26 = CONN_HDR_2X1: HDR 1X2 TH 100MIL SP 339H AU 98L; 3D_Mechanical_Footprint_File: ftp://fcl.am.freescale.net/ALLEGRO/step/hdr102_95l.STEP; AGILE_PN: 210-81490; CAD_APPROVED: Yes; HEIGHT: 8.59MM; MFG_NAME01: ANYTRONIC CORPORATION LIMITED; MFG_PN01: 0901S0202011N9T-31RF; ROHS: Yes; Temp Range: -55°C to +105°C; Temp_Range: -55°C to +105°C
J24 = KLPX0848A: CON 2 RCA SKT RA TH BLACK -- 512H SN; 3D_Mechanical_Footprint_File: ftp://fcl.am.freescale.net/ALLEGRO/step/con2_rca_ra_th.step; AGILE_PN: 210-78092; ASSY_OPT: DNP; CAD_APPROVED: Yes; HEIGHT: 13MM; MFG_NAME01: KYCON; MFG_PN01: KLPX-0848A-2-B; PRIORITY_PN: 009-00703; ROHS: Yes; SILK: SPDIF INPUT
J27 = KLPX0848A: CON 2 RCA SKT RA TH BLACK -- 512H SN; 3D_Mechanical_Footprint_File: ftp://fcl.am.freescale.net/ALLEGRO/step/con2_rca_ra_th.step; AGILE_PN: 210-78092; ASSY_OPT: DNP; CAD_APPROVED: Yes; HEIGHT: 13MM; MFG_NAME01: KYCON; MFG_PN01: KLPX-0848A-2-B; PRIORITY_PN: 009-00703; ROHS: Yes; SILK: SPDIF OUTPUT
R376 = RES: RES MF 100 OHM 1/16W 1% 0402; AGILE_PN: 470-30454; CAD_APPROVED: Yes; FPLIST: RC0402_25,RC0402_HD,0402_CC; HEIGHT: 0.4 MM; MFG_NAME01: THYE MING TECH CO LTD; MFG_PN01: CR-02FL6--100R; ROHS: Yes; Tolerance: 1%; VOLTAGE: 50V
R377 = RES: RES TF 75.0 OHM 1/8W 1% 0805; AGILE_PN: 470-76238; CAD_APPROVED: Yes; FPLIST: RC0805_OV,RC0805,0805_CC; HEIGHT: 0.6 MM; MFG_NAME01: YAGEO AMERICA; MFG_PN01: RC0805FR-0775RL; ROHS: Yes; TOL: 1%; Tolerance: 1%
R379 = RES: RES MF 374 OHM 1/8W 1% 0805; AGILE_PN: 470-80029; CAD_APPROVED: Yes; FPLIST: RC0805_OV,RC0805,0805_CC; HEIGHT: 0.5MM; MFG_NAME01: VISHAY INTERTECHNOLOGY; MFG_PN01: CRCW0805374RFKEA; ROHS: Yes; TOL: 1%; Tolerance: 1%
R380 = RES: RES MF 93.1 OHM 1/8W 1% AEC-Q200 0603; AGILE_PN: 470-77900; CAD_APPROVED: Yes; FPLIST: RC0603_OV,RC0603,0603_CC; HEIGHT: 0.55MM; MFG_NAME01: KOA SPEER; MFG_PN01: RK73H1JTTD93R1F; ROHS: Yes; TOL: 1%; Temp Range: -55C to +155C; Temp_Range: -55C to +155C; Tolerance: 1%
R381 = RES: RES MF ZERO OHM 1/16W 5% 0402; AGILE_PN: 470-75394; ASSY_OPT: DNP; CAD_APPROVED: Yes; FPLIST: RC0402_25,RC0402_HD,RC0402_X2,0402_CC; HEIGHT: 0.45 MM; MFG_NAME01: YAGEO AMERICA; MFG_PN01: RC0402JR-070RL; ROHS: Yes; Tolerance: 5%; VOLTAGE: 1/16W
T1 T2 = XFMR: XFMR SMT 780UH/780UH/250MA WIDEBAND XFMR6_6.6X6.2; AGILE_PN: 560-75273; ASSY_OPT: DNP; CAD_APPROVED: Yes; HEIGHT: 4.82MM; MFG_NAME01: COILCRAFT; MFG_PN01: TTWB1010LD; PART_TYPE: TRANSFORMERS; PRIORITY_PN: 051-TTWB1010LD; ROHS: Yes; ROOM: SPDIF
U22 = 74AUP2G06GW: IC INVERTER ULP-A DUAL 0.93.6V MICROPAK6; AGILE_PN: 315-81072; CAD_APPROVED: Yes; HEIGHT: 0.55MM; MFG_NAME01: FAIRCHILD; ROHS: Yes; VOLTAGE: 0.9-3.6V
U23 = 100201_SO-1: IC BUF TS 1.65-5.5V SOT-353; AGILE_PN: 312-30127; CAD_APPROVED: YES; HEIGHT: 1.1 MM; MFG_NAME01: ON SEMICONDUCTOR; MFG_PN01: NL17SZ126DFT2G; PRIORITY_PN: 051-NL17SZ126DF; ROHS: Yes; VOLTAGE: 2.3 to 3.6 V

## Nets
5V_SYS: C579.1 C580.1 U369.A2(SPKVDD1) U369.C2(SPKVDD2) ; also on sheet 5 6 19 20 24 25 26 27 29
GND: C92.2 C93.2 C94.2 C95.2 C96.2 C99.2 C100.2 C101.2 C102.2 C103.2 C104.2 C105.2 C106.2 C126.2 C167.2 C168.2 C401.2 C402.2 C403.2 C404.2 C405.2 C406.2 C407.2 C408.2 C409.2 C462.2 C463.2 C468.2 C469.2 C470.2 C471.2 C472.2 C473.2 C579.2 C580.2 C581.2 C582.2 C583.2 C584.2 C585.2 C586.2 C588.2 C589.2 C590.2 C591.2 C593.2 C594.1 C595.1 C598.2 C599.2 C602.2 C603.2 D46.2(A2) J15.6(VSS) J15.SH1(GND1) J15.SH2(GND2) J15.SH3(GND3) J15.SH4(GND4) J57.3 J58.3 J59.3 J67.11(A6) J67.12(B6) J71.7 J71.8 J71.11 J71.12 J71.15 J71.16 J71.19 J71.20 J71.23 J71.24 J71.SH1(29) J71.SH2(30) J71.SH3(31) J71.SH4(32) J75.3 J76.3 J101.5 R259.2 R260.2 R341.1 R377.2 R378.2 R382.2 R1043.2 R1046.1 R1048.2 R2137.2 R2146.2 R2147.2 R2148.2 R2149.2 R2150.2 R2151.2 R2156.1 T1.4 TP103.1(Pin1) U10.4(GND) U11.B3(VSS1) U11.C1(VSS2) U11.E5(VSS3) U12.4(GND) U13.4(GND) U22.2(GND) U23.3(GND) U63.5(GND) U64.5(GND) U65.5(GND) U66.5(GND) U67.5(GND) U68.5(GND) U69.5(GND) U70.5(GND) U71.5(GND) U116.3(GND) U117.3(GND) U118.3(GND) U119.3(GND) U369.B1(SPKGND1) U369.C1(SPKGND2) U369.C7(CPGND) U369.D7(AGND) U369.F2(CIFMODE) U369.F3(DGND) U369.G5(PLLGND) ; also on sheet 2 5 6 7 8 9 16 17 18 19 20 21 22 23 24 25 26 27 28 29 30 31
VDD_1V8: R2135.1 ; also on sheet 6 7 8 9 16 21 22 24
AUD_INT: R2145.2 ; also on sheet 8
CODEC_1V8: C583.1 C584.1 C585.1 C586.1 R2135.2 U369.C6(CPVDD) U369.D6(AVDD) U369.G2(DCVDD) U369.G4(PLLVDD)
CPCA: C587.1 U369.B6(CPCA)
CPCB: C587.2 U369.B7(CPCB)
CPVOUTN: C591.1 U369.A7(CPVOUTN)
CPVOUTP: C590.1 U369.A6(CPVOUTP)
DMIC_CLK: R1021.2 U116.4(CLOCK) U117.4(CLOCK) U118.4(CLOCK) U119.4(CLOCK) ; also on sheet 8
DMIC_DATA0: R343.2 R1022.1 ; also on sheet 8
DMIC_DATA1: R344.2 R1023.1 ; also on sheet 8
DMIC_DATA2: R348.2 R1024.1 ; also on sheet 8
DMIC_DATA3: R350.2 R1025.1 ; also on sheet 8
FDC_ECC: J71.2 TP50.1(TP)
FLASH_VCC: C99.1 C100.1 C101.1 C102.1 C103.1 C104.1 C471.1 C472.1 C473.1 J71.3 J71.4 J71.27 J71.28 R264.1 R266.1 R270.1 R287.1 R288.1 R289.1 R290.1 R291.1 R292.1 R294.1 R1091.1 R1093.1 TP102.1(Pin1) U10.8(VCC) U11.B4(VCC1) U11.C5(VPP) U11.D1(VCC2) U11.E4(VCC3) U12.8(VCC) ; also on sheet 6 8 22
FlexSPI1_A_CLK: TP67.1(Pin1) U69.7(COM2) ; also on sheet 8
FlexSPI1_A_CLK_4: U12.6(SCK) U69.2(A2)
FlexSPI1_A_CLK_8: R297.1 U69.4(B2)
FlexSPI1_A_D0: TP69.1(Pin1) U70.8(COM1) ; also on sheet 8
FlexSPI1_A_D0_4: U12.5(SI_IO0) U70.1(A1)
FlexSPI1_A_D0_8: U11.D3(DQ0) U70.3(B1)
FlexSPI1_A_D1: TP70.1(Pin1) U70.7(COM2) ; also on sheet 8
FlexSPI1_A_D1_4: U12.2(SO_IO1) U70.2(A2)
FlexSPI1_A_D1_8: U11.D2(DQ1) U70.4(B2)
FlexSPI1_A_D2: TP71.1(Pin1) U71.8(COM1) ; also on sheet 8
FlexSPI1_A_D2_4: R292.2 U12.3(~{WP}_IO2) U71.1(A1)
FlexSPI1_A_D2_8: U11.C4(DQ2/~{W}) U71.3(B1)
FlexSPI1_A_D3: TP72.1(Pin1) U71.7(COM2) ; also on sheet 8
FlexSPI1_A_D3_4: R291.2 U12.7(~{HOLD}/~{RESET}_IO3) U71.2(A2)
FlexSPI1_A_D3_8: U11.D4(DQ3) U71.4(B2)
FlexSPI1_A_D4: TP73.1(Pin1) U11.D5(DQ4) ; also on sheet 8
FlexSPI1_A_D5: TP74.1(Pin1) U11.E3(DQ5) ; also on sheet 8
FlexSPI1_A_D6: TP75.1(Pin1) U11.E2(DQ6) ; also on sheet 8
FlexSPI1_A_D7: TP76.1(Pin1) U11.E1(DQ7) ; also on sheet 8
FlexSPI1_A_DQS: R298.1 TP68.1(Pin1) ; also on sheet 8
FlexSPI1_A_SS0: U69.8(COM1) ; also on sheet 8
FlexSPI1_A_SS0_4: R290.2 U12.1(~{CE}) U69.1(A1)
FlexSPI1_A_SS0_8: R296.1 R312.1 U69.3(B1)
FlexSPI1_B_CLK: U66.7(COM2) ; also on sheet 8
FlexSPI1_B_CLK_4: U10.6(SCK) U66.2(A2)
FlexSPI1_B_CLK_8: J71.5 J71.6 U66.4(B2)
FlexSPI1_B_D0: U67.8(COM1) ; also on sheet 8
FlexSPI1_B_D0_4: U10.5(SI_IO0) U67.1(A1)
FlexSPI1_B_D0_8: J71.13 U67.3(B1)
FlexSPI1_B_D1: U67.7(COM2) ; also on sheet 8
FlexSPI1_B_D1_4: U10.2(SO_IO1) U67.2(A2)
FlexSPI1_B_D1_8: J71.14 U67.4(B2)
FlexSPI1_B_D2: U68.8(COM1) ; also on sheet 8
FlexSPI1_B_D2_4: R266.2 U10.3(~{WP}_IO2) U68.1(A1)
FlexSPI1_B_D2_8: J71.17 U68.3(B1)
FlexSPI1_B_D3: U68.7(COM2) ; also on sheet 8
FlexSPI1_B_D3_4: R264.2 U10.7(~{HOLD}/~{RESET}_IO3) U68.2(A2)
FlexSPI1_B_D3_8: J71.18 U68.4(B2)
FlexSPI1_B_D4: J71.21 ; also on sheet 8
FlexSPI1_B_D5: J71.22 ; also on sheet 8
FlexSPI1_B_D6: J71.25 ; also on sheet 8
FlexSPI1_B_D7: J71.26 ; also on sheet 8
FlexSPI1_B_DQS: J71.10 ; also on sheet 8
FlexSPI1_B_SS0: U66.8(COM1) ; also on sheet 8
FlexSPI1_B_SS0_4: R270.2 U10.1(~{CE}) U66.1(A1)
FlexSPI1_B_SS0_8: J71.9 R1091.2 U66.3(B1)
GPIO_AD_04: R904.1 ; also on sheet 8 27
GPIO_SD_B1_00: U63.8(COM1) ; also on sheet 8 26 27
GPIO_SD_B1_01: U63.7(COM2) ; also on sheet 8 26 27
GPIO_SD_B1_02: U64.8(COM1) ; also on sheet 8 26 27
GPIO_SD_B1_03: U64.7(COM2) ; also on sheet 8 26 27
GPIO_SD_B1_04: U65.8(COM1) ; also on sheet 8
GPIO_SD_B1_05: U65.7(COM2) ; also on sheet 8
HP_DET_B: D46.1(A1) J101.6 ; also on sheet 8
HPOUTL: C600.1 C602.1 L37.1 R2148.1 U369.B5(HPOUTL)
HPOUTL_ZOBEL: C600.2 R2150.1
HPOUTR: C601.1 C603.1 L38.1 R2149.1 U369.A5(HPOUTR)
HPOUTR_ZOBEL: C601.2 R2151.1
IN3R: C592.2 U369.F6(IN3R)
LPI2C2_SCL: U369.F1(SCLK) ; also on sheet 8 21 26 29
LPI2C2_SDA: U369.E2(SDA) ; also on sheet 8 21 26 29
LPSPI1_PCS0: R314.1 ; also on sheet 8
LPSPI1_SCK: R318.1 ; also on sheet 8
LPSPI1_SDI: R315.1 ; also on sheet 8
LPSPI1_SDO: R319.1 ; also on sheet 8
MICBIAS: C589.1 R2136.1 U369.A4(MICBIAS)
MICVDD: C582.1 R2134.2 U369.A3(MICVDD)
OCT_FLASH_RST_B: R293.1 R1094.1 ; also on sheet 22
OE_FlexSPI1_A_EN: J59.2 U69.6(~{EN}) U70.6(~{EN}) U71.6(~{EN})
OE_FlexSPI1_B_EN: J58.2 U66.6(~{EN}) U67.6(~{EN}) U68.6(~{EN})
OE_SD_SDIO_EN: J57.2 U63.6(~{EN}) U64.6(~{EN}) U65.6(~{EN})
QSPI0_OCT1_SEL_A: J75.2 U69.9(SEL) U70.9(SEL) U71.9(SEL)
QSPI0_OCT1_SEL_B: R904.2 U66.9(SEL) U67.9(SEL) U68.9(SEL)
SAI1_MCLK: R2140.1 ; also on sheet 8
SAI1_RX_BCLK: R2138.2 ; also on sheet 8
SAI1_RX_SYNC: R2139.2 ; also on sheet 8
SAI1_RXD[0]: J99.1 ; also on sheet 8
SAI1_TX_BCLK: J98.1 ; also on sheet 8
SAI1_TX_SYNC: J97.1 ; also on sheet 8
SAI1_TXD[0]: J100.1 ; also on sheet 8
SD1_CD_B: R257.2 ; also on sheet 8
SD1_CLK: C95.1 R258.1 U63.4(B2)
SD1_CMD: J15.3(CMD) U63.3(B1)
SD1_D0: J15.7(DAT0) U64.3(B1)
SD1_D1: J15.8(DAT1) U64.4(B2)
SD1_D2: J15.1(DAT2) U65.3(B1)
SD1_D3: J15.2(CD/DAT3) R260.1 U65.4(B2)
SDIO0_SD1_SEL: J76.2 U63.9(SEL) U64.9(SEL) U65.9(SEL)
SENSOR_3V3: C105.1 C106.1 C126.1 C401.1 C402.1 C403.1 C404.1 C405.1 C406.1 C407.1 C408.1 C409.1 C462.1 C463.1 C468.1 C469.1 C470.1 C581.1 J23.2 J57.1 J58.1 J59.1 J67.1(A1) J67.2(B1) J75.1 J76.1 R256.1 R313.1 R316.1 R317.1 R339.1 R1044.2 R1045.1 R1047.2 R2134.1 U13.8(VCC) U63.10(VCC) U64.10(VCC) U65.10(VCC) U66.10(VCC) U67.10(VCC) U68.10(VCC) U69.10(VCC) U70.10(VCC) U71.10(VCC) U116.5(VDD) U117.5(VDD) U118.5(VDD) U119.5(VDD) U369.G3(DBVDD) ; also on sheet 2 5 6 7 8 9 16 17 18 19 20 21 22 23 24 25 26 27 28 29 30 31
SPDIF_BUF: R379.1 R381.2 U23.4(Y)
SPDIF_COAX_OUT: J27.2 T2.1
SPDIF_EXT_CLK: TP18.1(TP) ; also on sheet 8
SPDIF_GND_PRI: R380.2 R382.1 T2.4
SPDIF_IN: J25.1 ; also on sheet 8
SPDIF_LOCK: TP16.1(TP) ; also on sheet 8
SPDIF_OUT: J26.2 ; also on sheet 8
SPDIF_OUT_PRI: C169.2 R380.1 T2.6
SPDIF_SR_CLK: TP17.1(TP) ; also on sheet 8
SPDIF_VCC: C167.1 C168.1 J23.1 U22.5(VCC) U23.1(OE) U23.5(VCC)
SPK_LN: R2142.1 U369.B3(SPKOUTLN)
SPK_LP: R2144.1 U369.A1(SPKOUTLP)
SPK_RN: R2141.1 U369.C3(SPKOUTRN)
SPK_RP: R2143.1 U369.B2(SPKOUTRP)
VSD_3V3: C92.1 C93.1 C94.1 J15.4(VDD) ; also on sheet 6
WIFI_SDIO_CLK: U63.2(A2) ; also on sheet 21
WIFI_SDIO_CMD: U63.1(A1) ; also on sheet 21
WIFI_SDIO_D0: U64.1(A1) ; also on sheet 21
WIFI_SDIO_D1: U64.2(A2) ; also on sheet 21
WIFI_SDIO_D2: U65.1(A1) ; also on sheet 21
WIFI_SDIO_D3: U65.2(A2) ; also on sheet 21
N100728650: J15.9(DETECT) R256.2 R257.1 R259.1
N100768470: C96.1 J15.5(CLK) R258.2
N101248699: R339.2 R341.2 U116.2(SELECT)
N101250307: C165.1 J24.2
N101250309: J24.1 T1.3
N101250379: R375.1 R376.2 U22.1(1A)
N101250387: C165.2 T1.1
N101250389: C166.1 R377.1 T1.6
N101250395: C166.2 R376.1
N101250397: R375.2 R378.1 U22.3(2A) U22.6(1Y)
N101250409: J25.2 U22.4(2Y)
N101250428: J26.1 R381.1 U23.2(A)
N101250468: J27.1 T2.3
N101293462: R343.1 R348.1 U116.1(DATA) U117.1(DATA)
N101293775: R344.1 R350.1 U118.1(DATA) U119.1(DATA)
N103609194: R2156.2 U11.B1(RFU_3)
N103609206: R299.2 U11.A5(RFU_2)
N103609208: R303.2 U11.A2(NC)
N103609210: R308.2 U11.A3(RFU_1)
N103609334: R289.2 R303.1 R308.1 R312.2
N103609361: R288.2 R296.2 U11.C2(~{S})
N103609367: R287.2 R293.2 U11.A4(~{RESET})
N103609386: R298.2 U11.C3(DQS)
N103609426: R297.2 U11.B2(C)
N103609440: R294.2 R299.1
N103789758: R316.2 U13.7(~{HOLD})
N103789768: R318.2 U13.6(SCLK)
N103789772: R319.2 U13.5(SI/SIO0)
N103789774: R317.2 U13.3(~{WP})
N103789776: R313.2 R314.2 U13.1(~{CS})
N103789794: R315.2 U13.2(SO/SIO1)
N105054073: J67.3(A2) J67.5(A3) J67.7(A4) J67.9(A5) R1021.1
N105054132: J67.4(B2) R1022.2
N105054134: J67.6(B3) R1023.2
N105054136: J67.8(B4) R1024.2
N105054138: J67.10(B5) R1025.2
N105164696: R1043.1 R1044.1 U117.2(SELECT)
N105165362: R1045.2 R1046.2 U118.2(SELECT)
N105165453: R1047.1 R1048.1 U119.2(SELECT)
N105401122: J71.1 R1093.2 R1094.2
N106204967: TP1024.1(TP) U369.C4(IN1L)
N106204969: C593.1 U369.D4(IN1R)
N106205008: TP1025.1(TP) U369.D5(IN2L)
N106205010: TP1026.1(TP) U369.E5(IN2R)
N106205029: C592.1 P2.1(Out) R2136.2
N106205042: TP1027.1(TP) U369.F5(IN3L)
N106205065: TP1028.1(TP) U369.E6(IN4L)
N106205067: P2.2(GND) R2137.1
N106205081: TP1029.1(TP) U369.E7(IN4R)
N106205130: J98.2 R2138.1 U369.E1(BCLK)
N106205151: J97.2 R2139.1 U369.D3(LRCLK)
N106205159: J100.2 U369.D1(DACDAT)
N106205163: J99.2 U369.D2(ADCDAT)
N106205177: R2140.2 U369.G7(MCLK/XTI)
N106205193: TP1030.1(TP) U369.F7(XTO)
N106205804: C594.2 C596.1 J95.1 R2141.2
N106205806: C595.2 C597.1 J96.1 R2142.2
N106205931: C596.2 C598.1 J95.2 R2143.2
N106205933: C597.2 C599.1 J96.2 R2144.2
N106205994: TP1022.1(TP) U369.E4(CLKOUT2/GPIO2)
N106206003: TP1023.1(TP) U369.F4(CLKOUT3/GPIO3)
N106206005: R2146.1 U369.G1(GPIO5)
N106206024: R2145.1 U369.E3(~{CS}/GPIO6)
N106206063: TP1031.1(TP) U369.G6(CLKOUT5)
N106206071: C588.1 U369.C5(VMIDC)
N106207432: J101.4 L37.2
N106207455: J101.1 L38.2
N106207457: R2147.1 U369.B4(HPOUTFB)
N107446247: C169.1 R379.2

Not connected (* = marked no-connect by the designer): U11 B5(RFU_4)*

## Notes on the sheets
sheet 10
- SEL_0  COM to A Port
  SEL_1  COM to B Port
- Default:1-2
- Default:2-3
- SD Card Socket
- FOR SD BOOT, ROM NEED SD_CD_SW PIN KEPT LOW
  ===========================================
  CARD INSERT-->SD1_CD_B LOW
  CARD OFF-->SD1_CD_B HIGH
- Place close to MCU
sheet 11
- FlexSPI1_A
- SEL_0  COM to A Port
  SEL_1  COM to B Port
- Default:2-3
- Default:2-3
- Those TPs are Reserved for FlexSPI Extension
  Be placed tegether in order
- MAX 180 mA @1.8V
- Share the same package with S27KS0641DPBHI023
  (if HYPERRAM is used, DNP R299/R303,Mount R308/R312)
- FlexSPI1_B
- Default:2-3
- FLASH DAUGHTER CARD
sheet 12
- LPSPI Flash(Secondary Boot)
sheet 13
- Board DMIC
- 8CH-DMIC Extension
- Notes: Placing the mic under PCB which is opening to face the user
- L/R->VCC, LEFT CHANNEL
- L/R->VCC, LEFT CHANNEL
- L/R->GND, RIGHT CHANNEL
- L/R->GND, RIGHT CHANNEL
sheet 14
- Audio Codec
- Layout note:
  Widen the trace SPKVDD
  Max ~0.6A
- HeadPhone
- Layout note:
  Route HPOUT_FB between HPOUTR and HPOUTL
  R2147 close to J101
- Layout note:
  C602 & C603 close to HP Jack, for EMI purpose
- Layout note:
  Zobel Networks(C600,C601,R2150,R2151) close to WM8962
- Speaker
- layout note:
  C587 should be as close to the WM8962 as possible.
- or WM-63PR
  or CMC-2242PBL-A
- Default:1-2
- Default:1-2
- Default:1-2
- Default:1-2
sheet 15
- SPDIF Interface
- Default:Open
- SPDIF COAX INPUT
- Default:Open
- SPDIF COAX OUTPUT
- Default:Open
